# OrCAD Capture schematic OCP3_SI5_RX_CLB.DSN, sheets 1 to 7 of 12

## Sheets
1 PAGE01: title: OCP3 SI GEN 5 RX CLB; rev: X02; company: Dell, Inc.; note: C7D95; note: 200 Dell Way; note: Round Rock, TX 78682
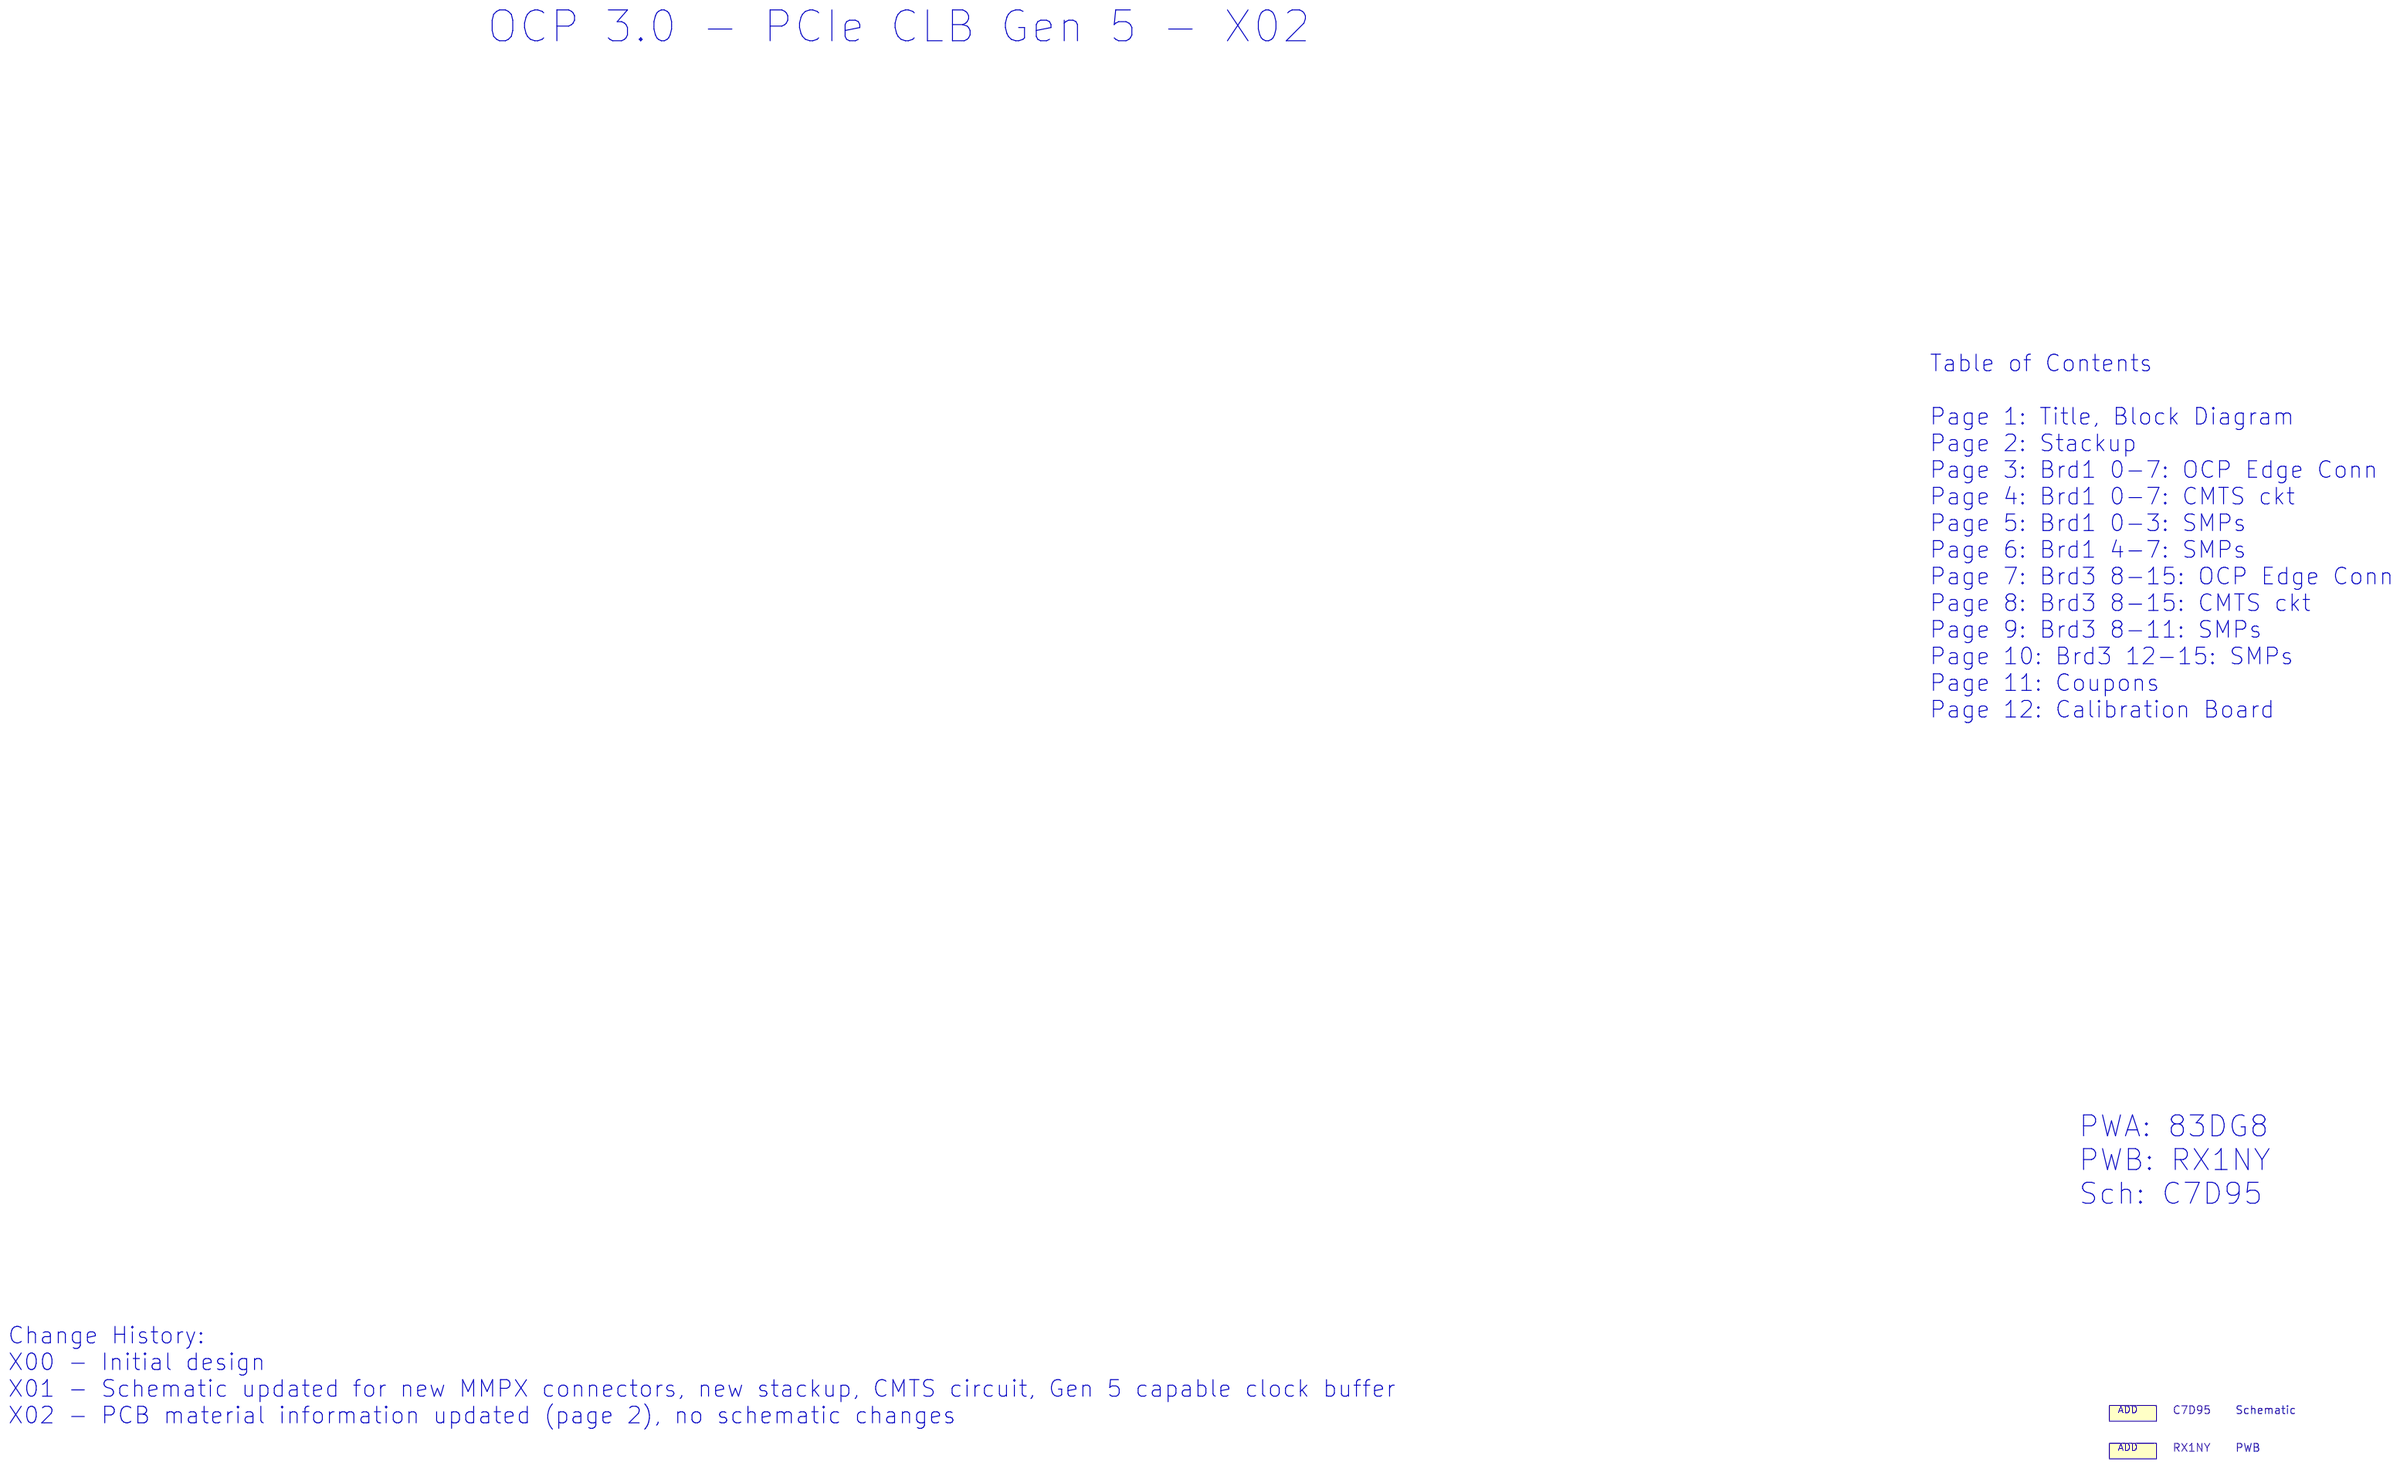
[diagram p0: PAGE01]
2 PAGE02
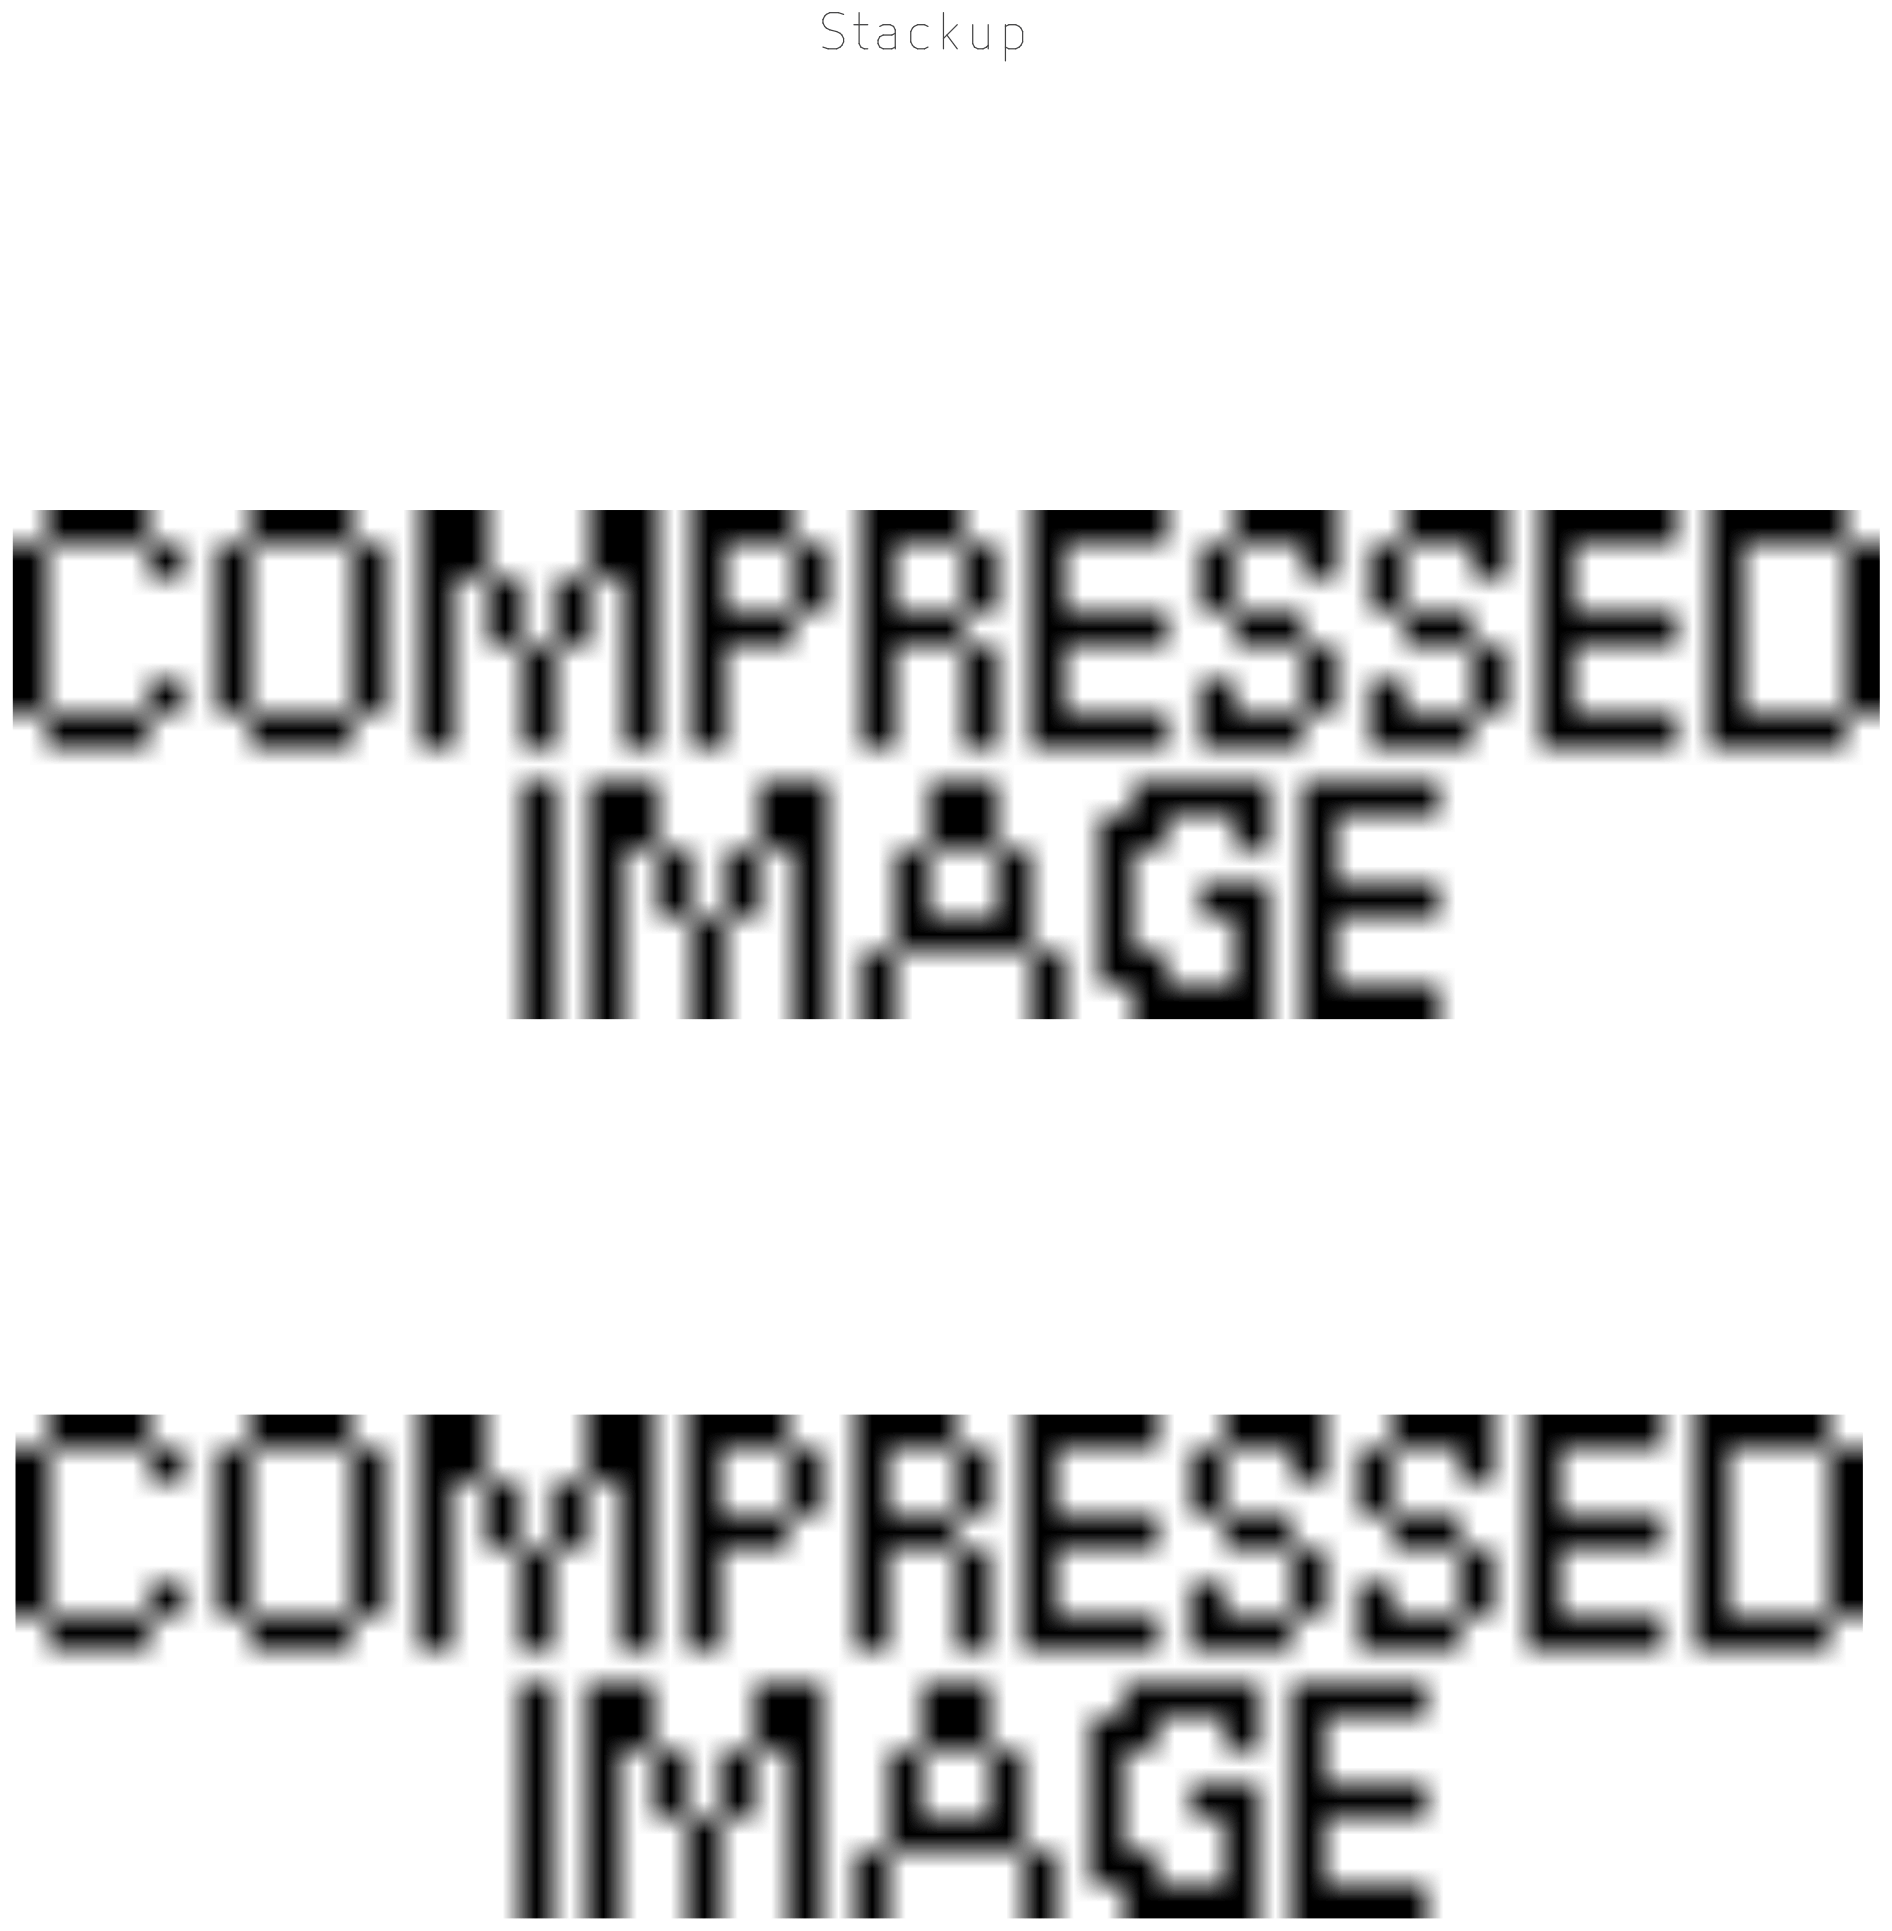
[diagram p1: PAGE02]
3 PAGE03: size Custom
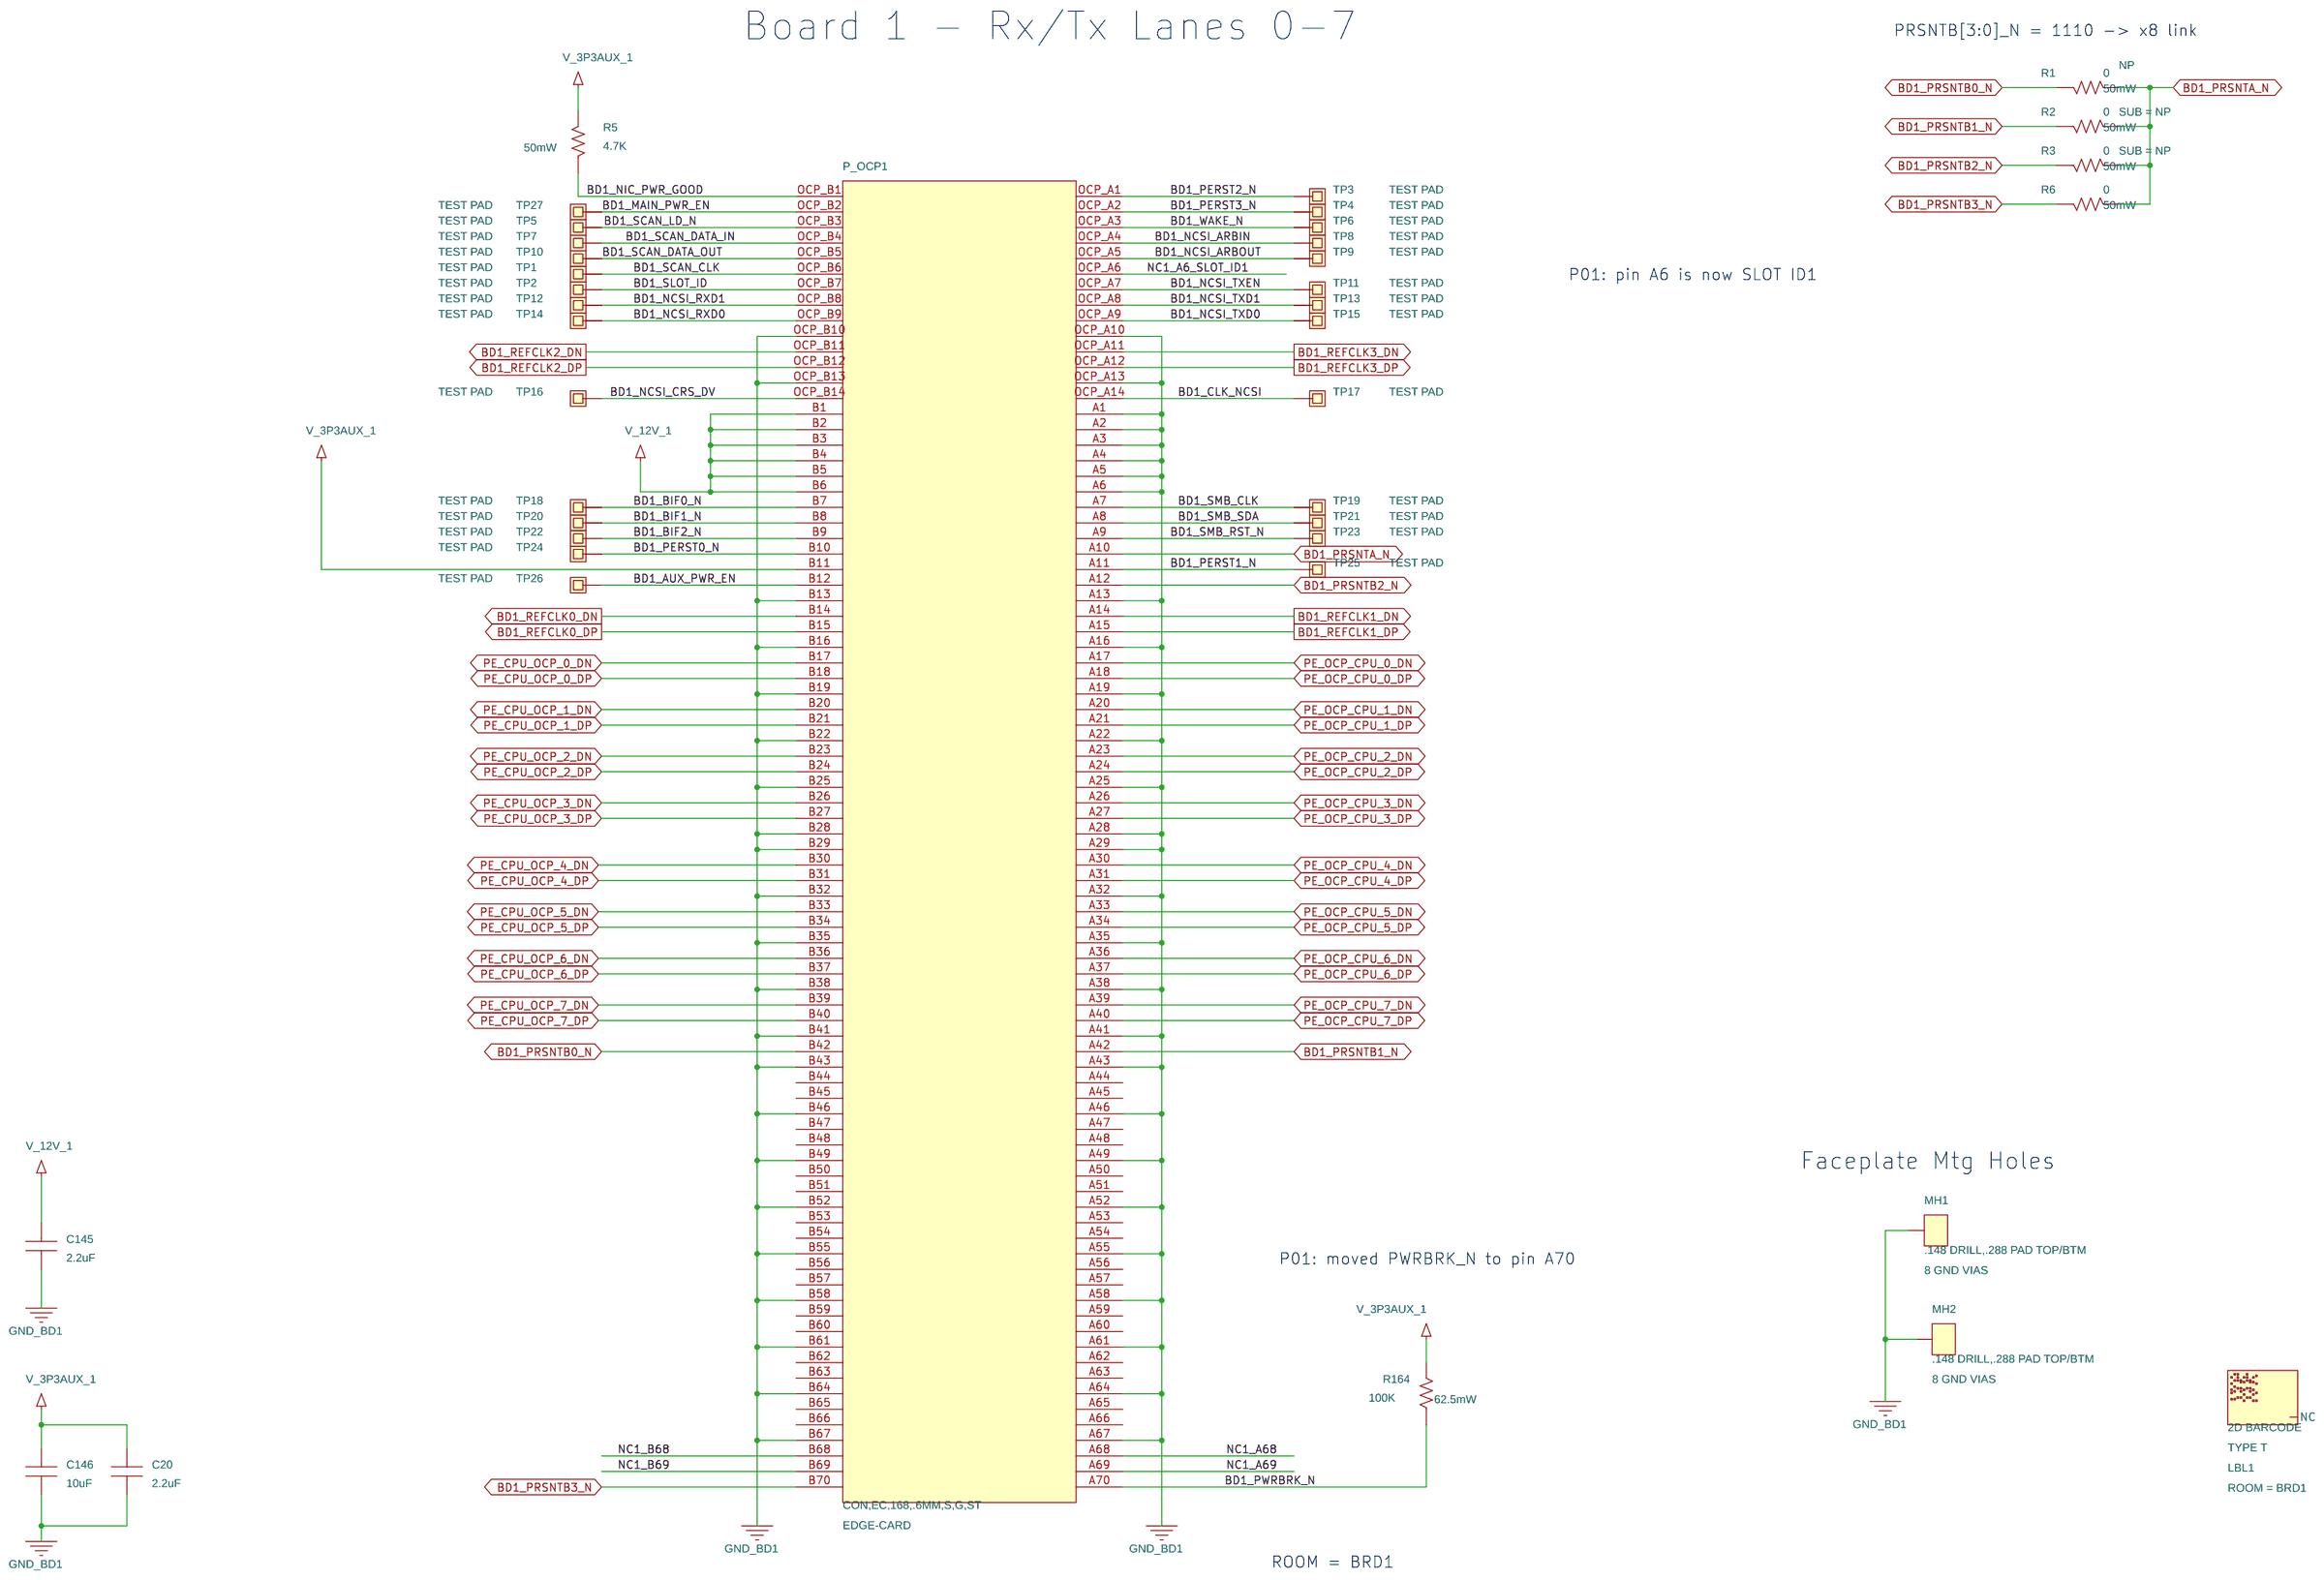
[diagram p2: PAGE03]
4 PAGE04: size Custom
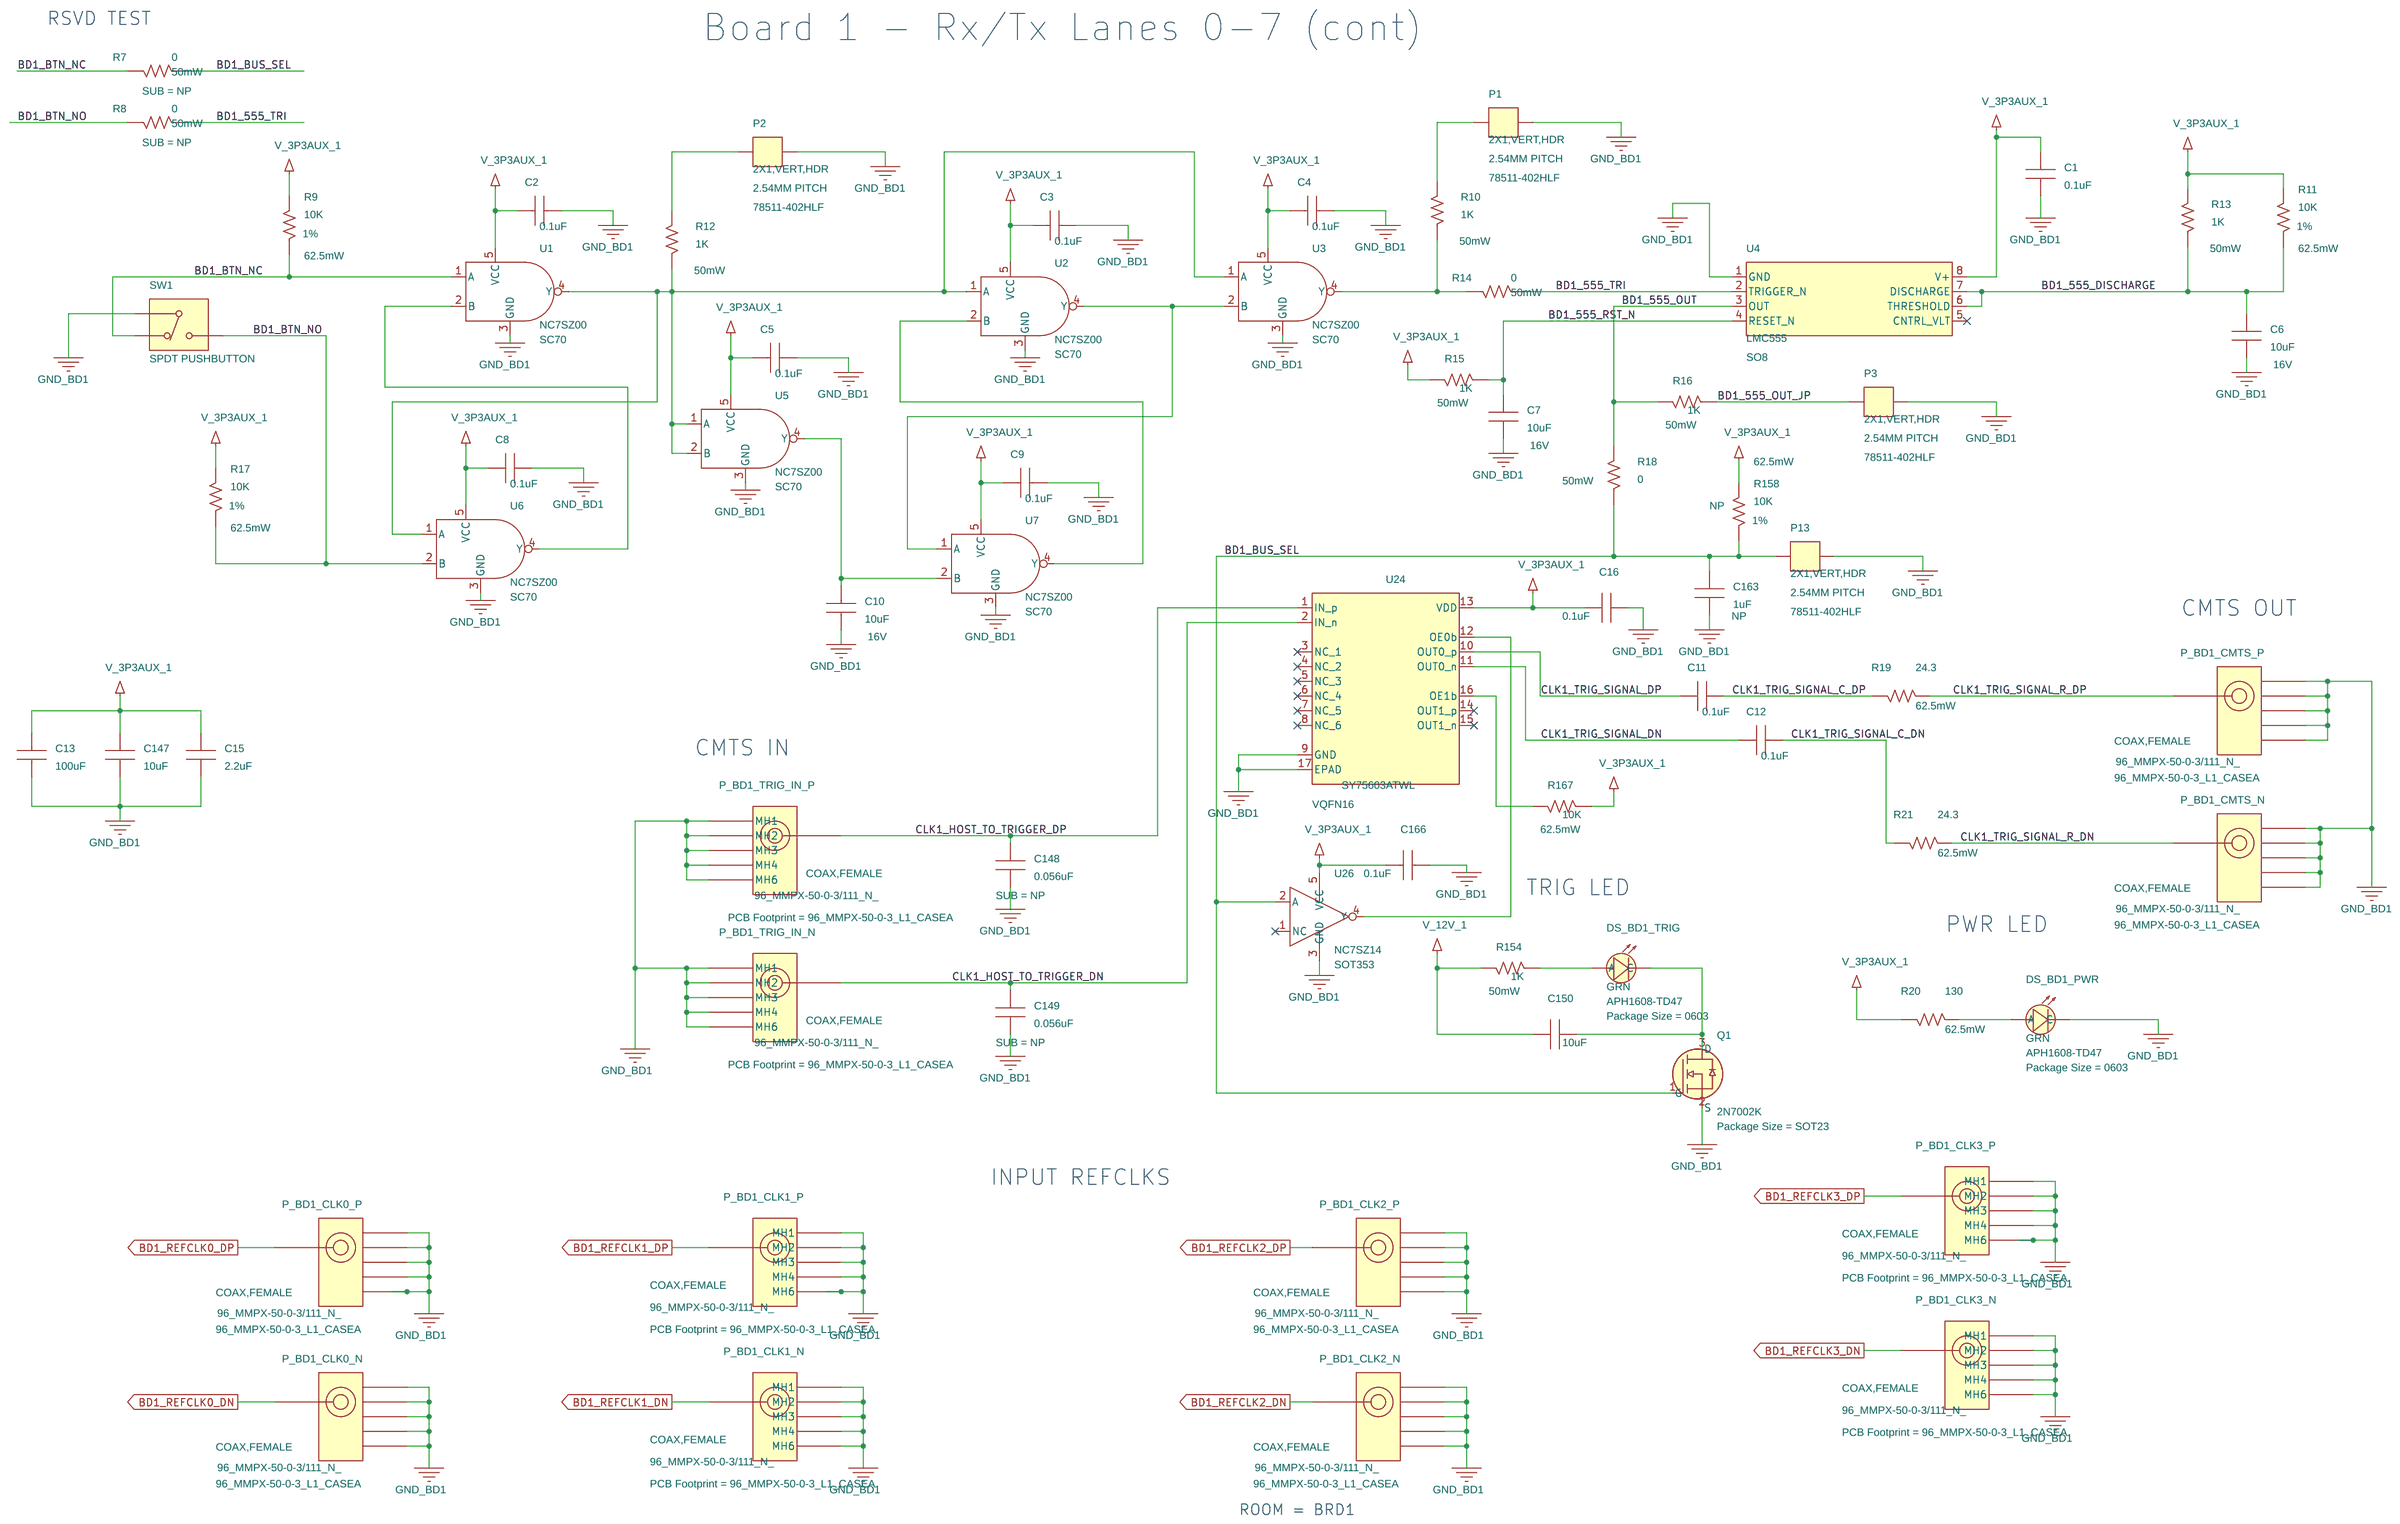
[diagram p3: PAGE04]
5 PAGE05: size Custom
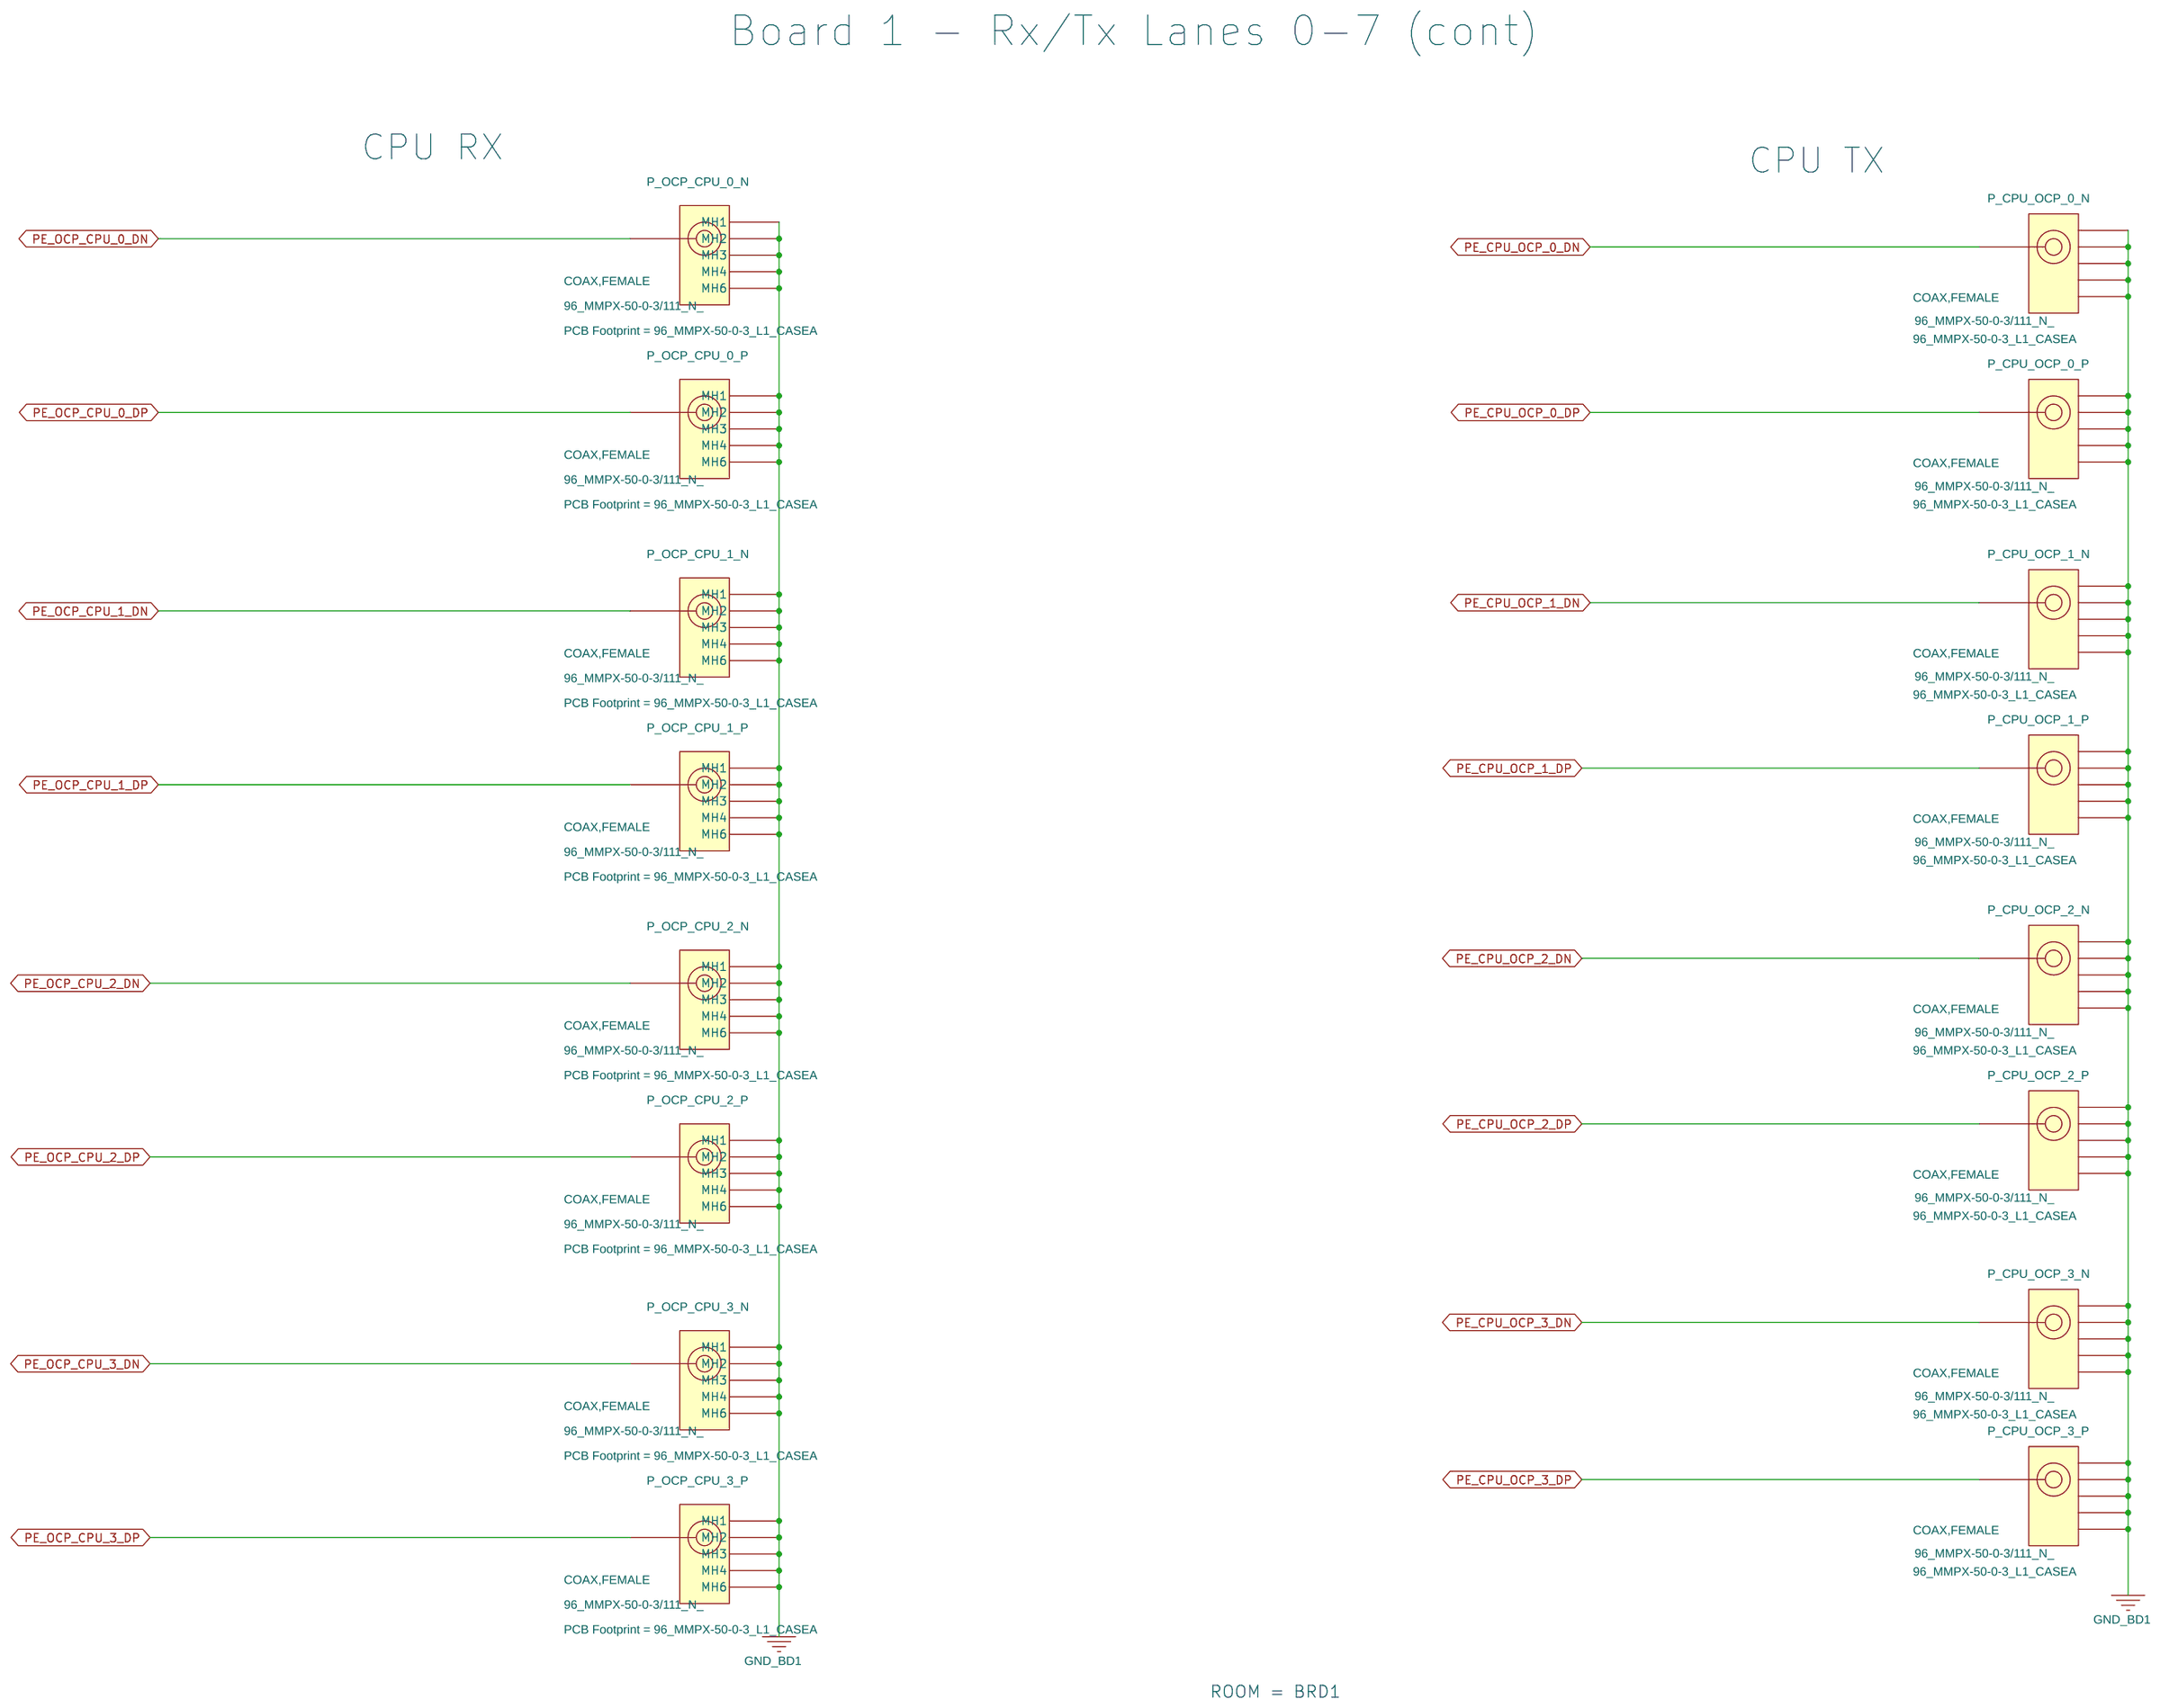
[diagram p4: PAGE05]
6 PAGE06: size Custom
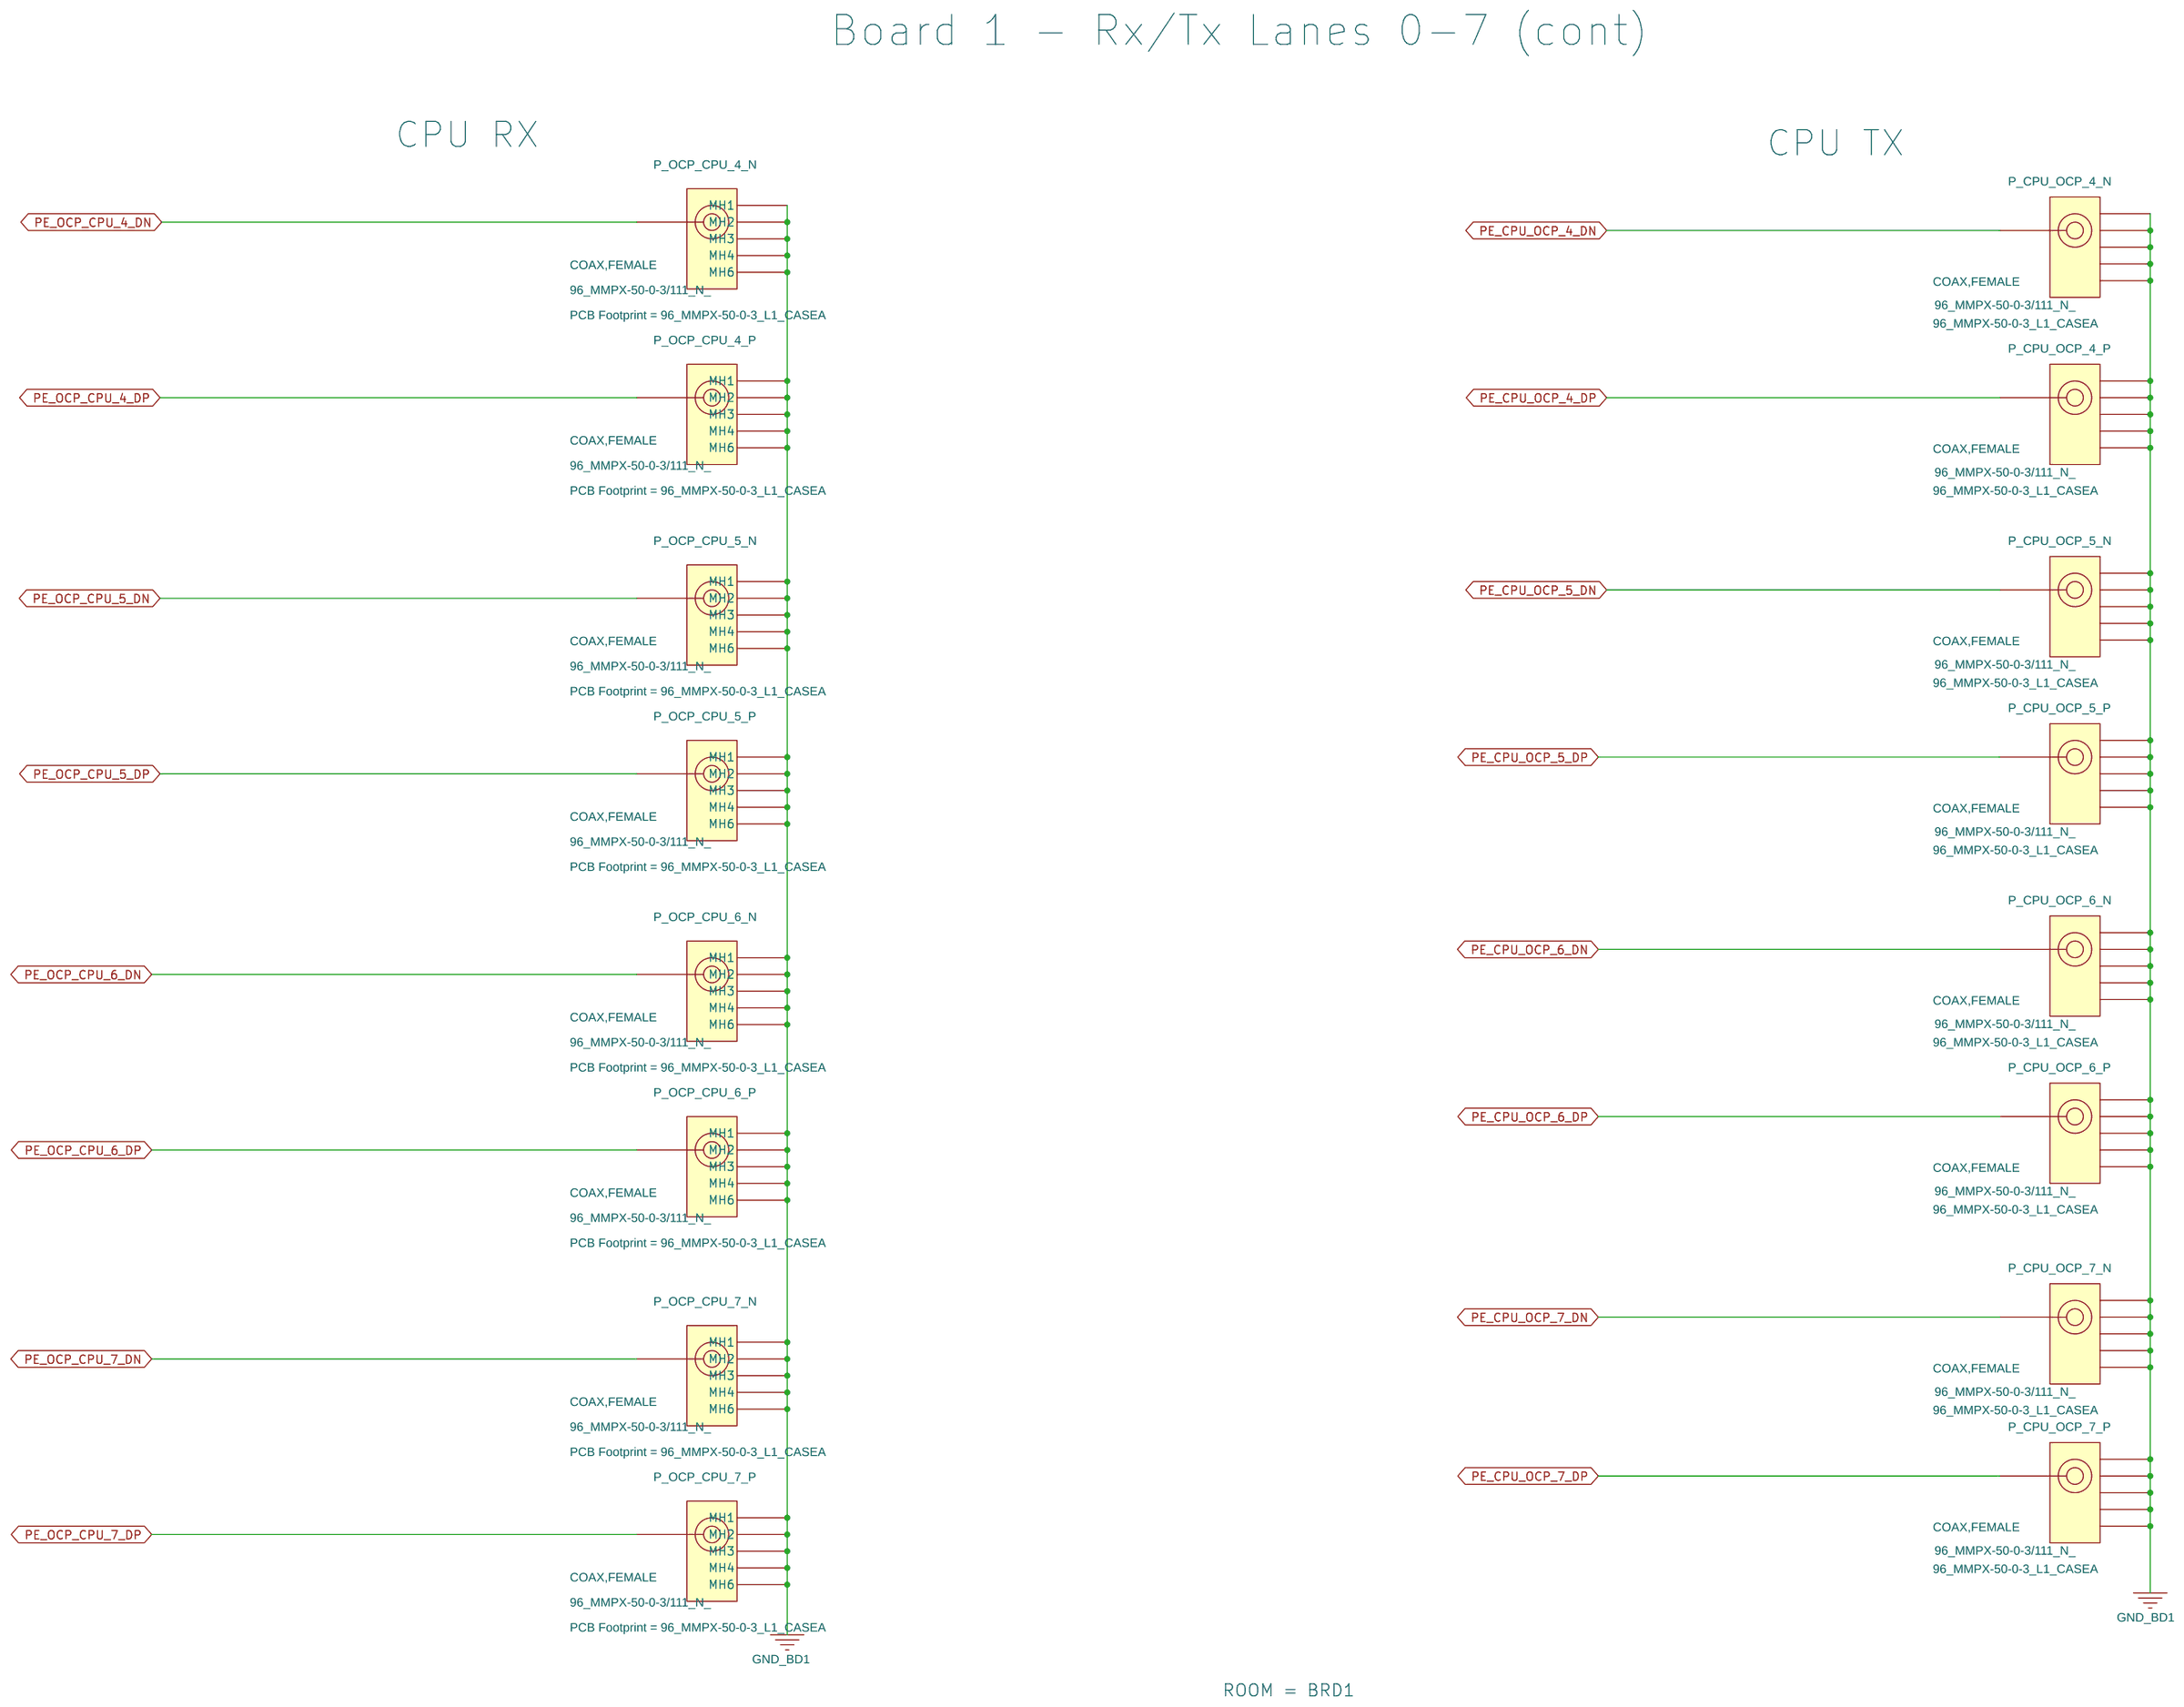
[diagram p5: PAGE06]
7 PAGE07: size Custom
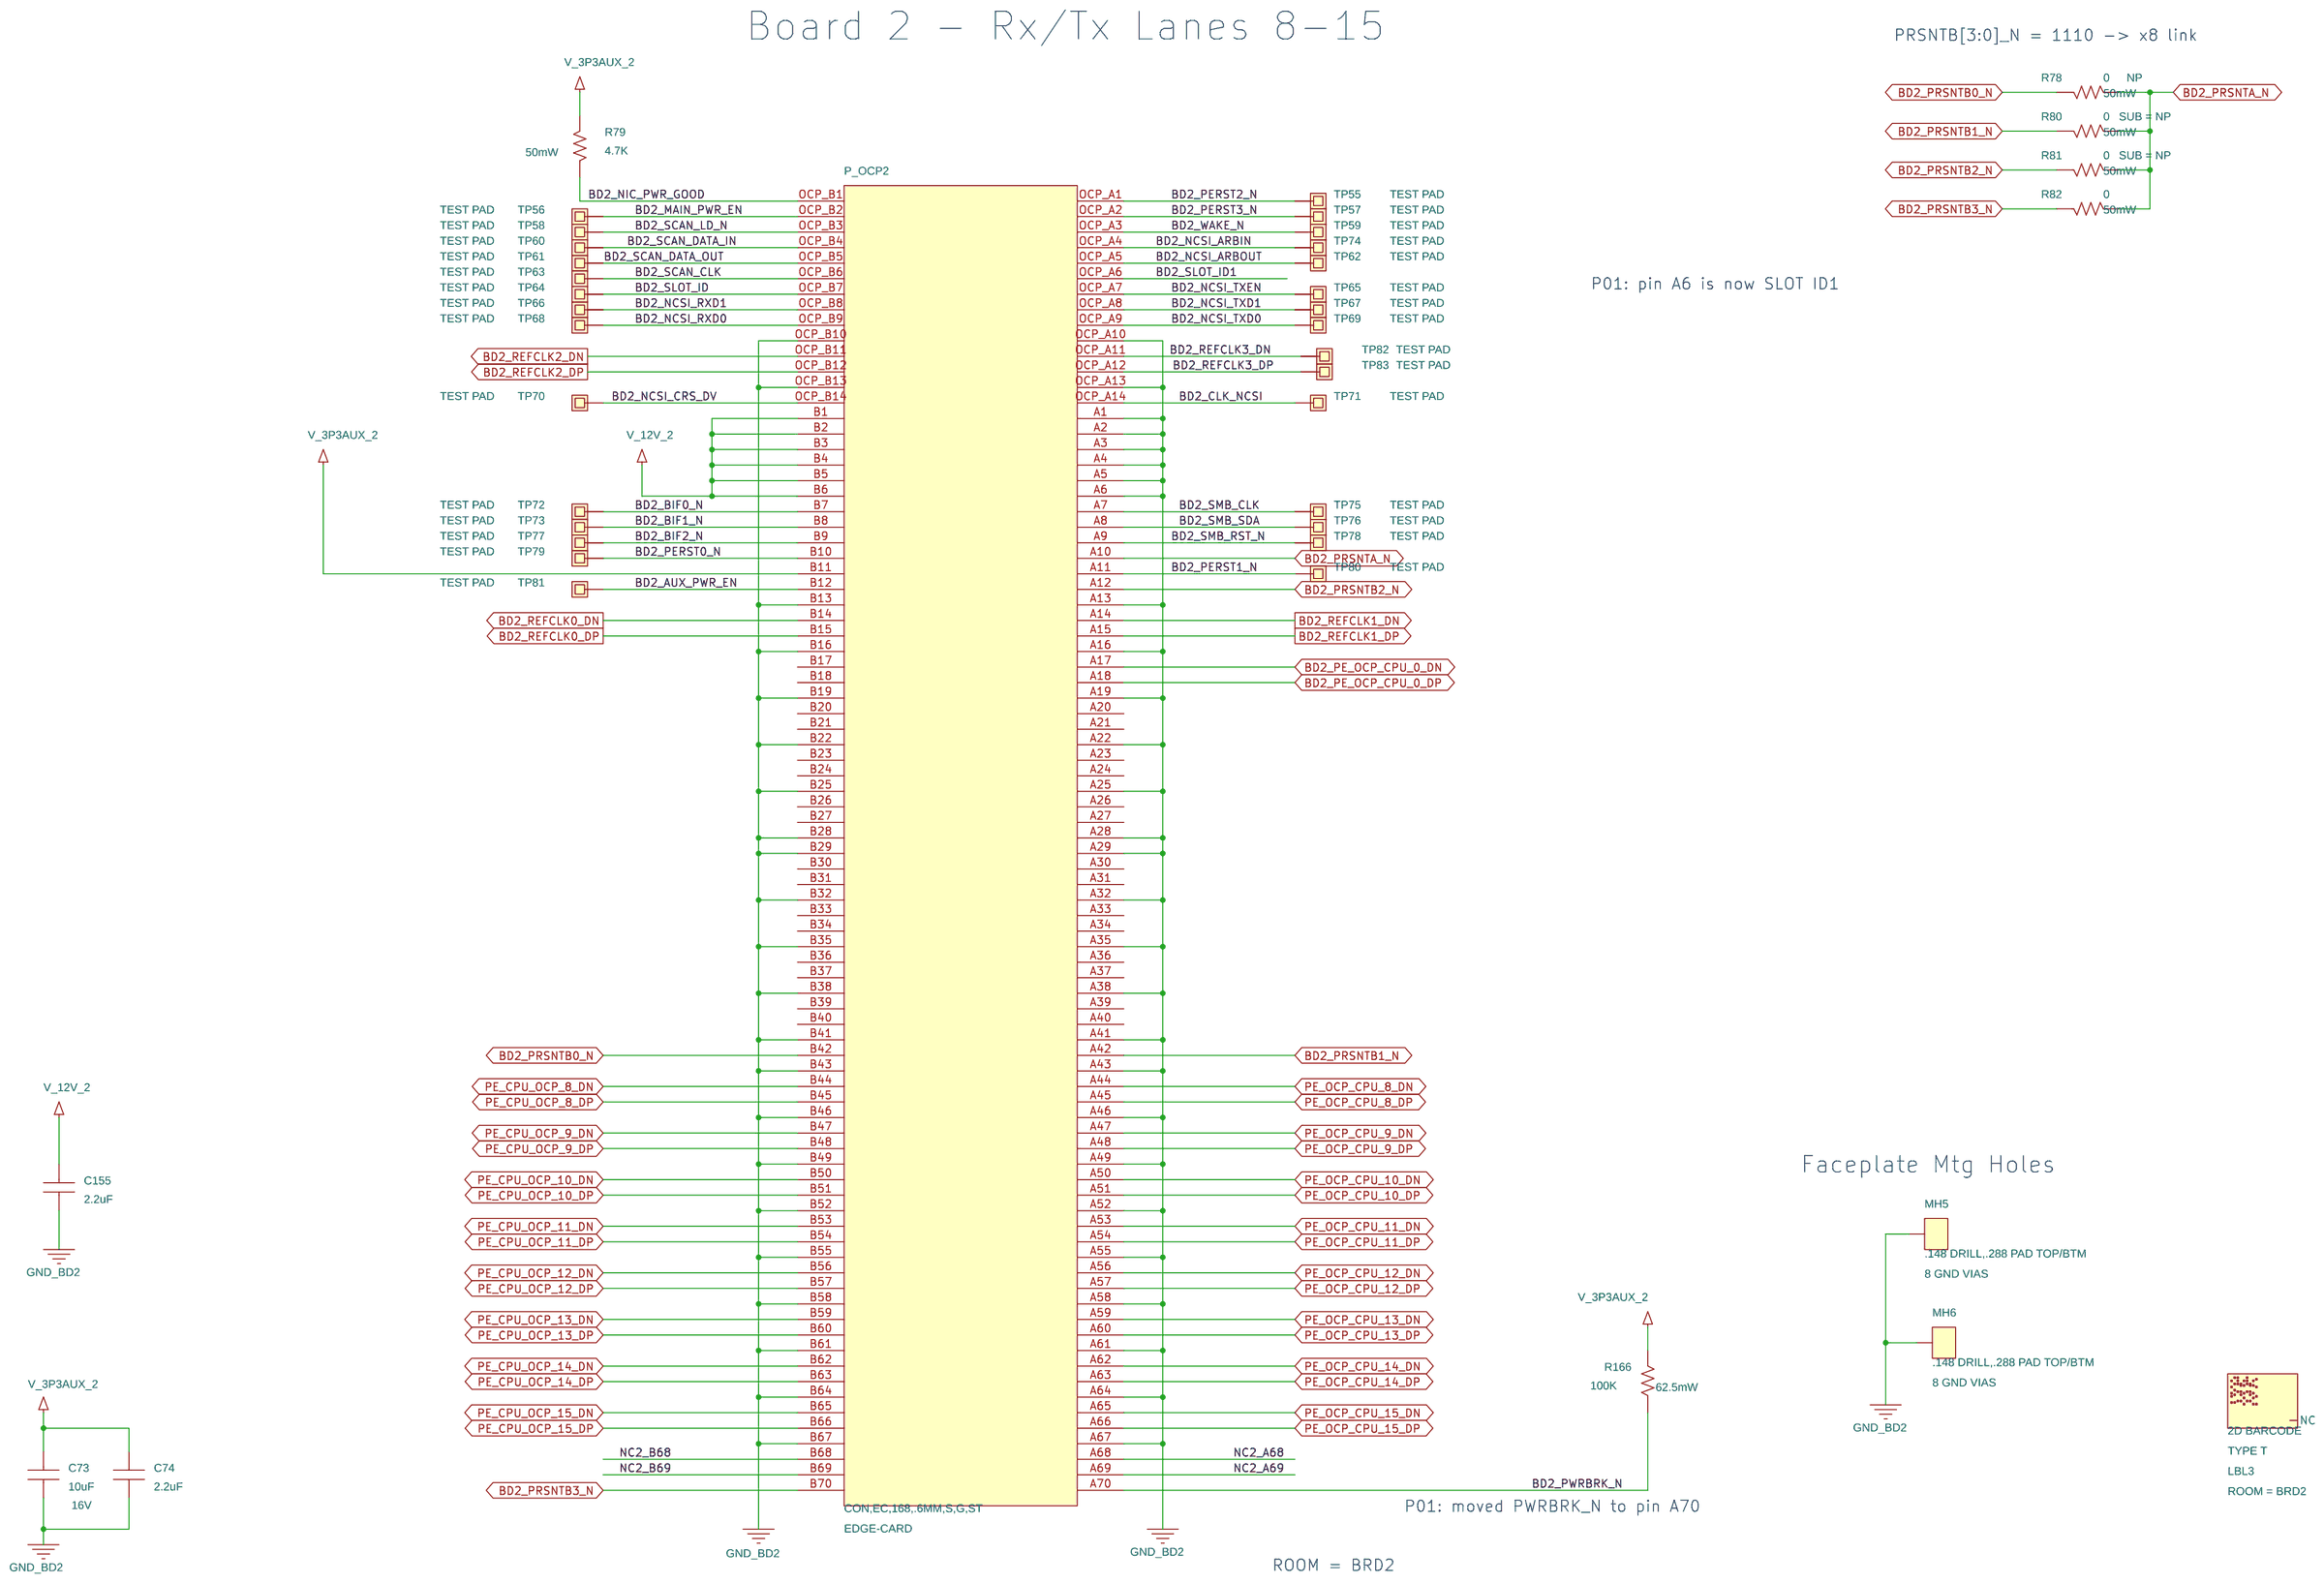
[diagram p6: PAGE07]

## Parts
sheet PAGE01
PWB  add_part
Schematic  add_part
sheet PAGE03
C20  2.2uF  [C0603]
C145  2.2uF  [C0603]
C146  10uF  [C0603]
LBL1  2d_label500x437  [2D_LABEL500X437]
MH1  .148 DRILL,.288 PAD TOP/BTM  [MH148_G8_288TB]
MH2  .148 DRILL,.288 PAD TOP/BTM  [MH148_G8_288TB]
P_OCP1  CON,EC,168,.6MM,S,G,ST  [CON_AMP_EDGE_ME101681340131X]
R1  0  [R0201]
R2  0  [R0201]
R3  0  [R0201]
R5  4.7K  [R0201]
R6  0  [R0201]
R164  100K  [R0402]
TP1  TEST PAD  [TP_REC1P00X1P50]
TP2  TEST PAD  [TP_REC1P00X1P50]
TP3  TEST PAD  [TP_REC1P00X1P50]
TP4  TEST PAD  [TP_REC1P00X1P50]
TP5  TEST PAD  [TP_REC1P00X1P50]
TP6  TEST PAD  [TP_REC1P00X1P50]
TP7  TEST PAD  [TP_REC1P00X1P50]
TP8  TEST PAD  [TP_REC1P00X1P50]
TP9  TEST PAD  [TP_REC1P00X1P50]
TP10  TEST PAD  [TP_REC1P00X1P50]
TP11  TEST PAD  [TP_REC1P00X1P50]
TP12  TEST PAD  [TP_REC1P00X1P50]
TP13  TEST PAD  [TP_REC1P00X1P50]
TP14  TEST PAD  [TP_REC1P00X1P50]
TP15  TEST PAD  [TP_REC1P00X1P50]
TP16  TEST PAD  [TP_REC1P00X1P50]
TP17  TEST PAD  [TP_REC1P00X1P50]
TP18  TEST PAD  [TP_REC1P00X1P50]
TP19  TEST PAD  [TP_REC1P00X1P50]
TP20  TEST PAD  [TP_REC1P00X1P50]
TP21  TEST PAD  [TP_REC1P00X1P50]
TP22  TEST PAD  [TP_REC1P00X1P50]
TP23  TEST PAD  [TP_REC1P00X1P50]
TP24  TEST PAD  [TP_REC1P00X1P50]
TP25  TEST PAD  [TP_REC1P00X1P50]
TP26  TEST PAD  [TP_REC1P00X1P50]
TP27  TEST PAD  [TP_REC1P00X1P50]
sheet PAGE04
C1  0.1uF  [C0201]
C2  0.1uF  [C0201]
C3  0.1uF  [C0201]
C4  0.1uF  [C0201]
C5  0.1uF  [C0201]
C6  10uF  [C0603]
C7  10uF  [C0603]
C8  0.1uF  [C0201]
C9  0.1uF  [C0201]
C10  10uF  [C0603]
C11  0.1uF  [C0201]
C12  0.1uF  [C0201]
C13  100uF  [C1210_107H]
C15  2.2uF  [C0603]
C16  0.1uF  [C0201]
C147  10uF  [C0603]
C148  0.056uF  [C0402]
C149  0.056uF  [C0402]
C150  10uF  [C0603]
C163  1uF  [C0603]
C166  0.1uF  [C0201]
DS_BD1_PWR  APH1608-TD47  [LEDC1608X65N]
DS_BD1_TRIG  APH1608-TD47  [LEDC1608X65N]
P1  2X1,VERT,HDR  [BERG1X2]
P2  2X1,VERT,HDR  [BERG1X2]
P3  2X1,VERT,HDR  [BERG1X2]
P13  2X1,VERT,HDR  [BERG1X2]
P_BD1_CLK0_N  COAX,FEMALE  [96_MMPX-50-0-3_L1_CASEA]
P_BD1_CLK0_P  COAX,FEMALE  [96_MMPX-50-0-3_L1_CASEA]
P_BD1_CLK1_N  COAX,FEMALE  [96_MMPX-50-0-3_L1_CASEA]
P_BD1_CLK1_P  COAX,FEMALE  [96_MMPX-50-0-3_L1_CASEA]
P_BD1_CLK2_N  COAX,FEMALE  [96_MMPX-50-0-3_L1_CASEA]
P_BD1_CLK2_P  COAX,FEMALE  [96_MMPX-50-0-3_L1_CASEA]
P_BD1_CLK3_N  COAX,FEMALE  [96_MMPX-50-0-3_L1_CASEA]
P_BD1_CLK3_P  COAX,FEMALE  [96_MMPX-50-0-3_L1_CASEA]
P_BD1_CMTS_N  COAX,FEMALE  [96_MMPX-50-0-3_L1_CASEA]
P_BD1_CMTS_P  COAX,FEMALE  [96_MMPX-50-0-3_L1_CASEA]
P_BD1_TRIG_IN_N  COAX,FEMALE  [96_MMPX-50-0-3_L1_CASEA]
P_BD1_TRIG_IN_P  COAX,FEMALE  [96_MMPX-50-0-3_L1_CASEA]
Q1  2N7002K  [SOT95P237X117_3N]
R7  0  [R0201]
R8  0  [R0201]
R9  10K  [R0402]
R10  1K  [R0201]
R11  10K  [R0402]
R12  1K  [R0201]
R13  1K  [R0201]
R14  0  [R0201]
R15  1K  [R0201]
R16  1K  [R0201]
R17  10K  [R0402]
R18  0  [R0201]
R19  24.3  [R0402]
R20  130  [R0402]
R21  24.3  [R0402]
R154  1K  [R0201]
R158  10K  [R0402]
R167  10K  [R0402]
SW1  SPDT PUSHBUTTON  [SW3PSMRA_2SH]
U1  NC7SZ00  [SOT65P210X110_5N]
U2  NC7SZ00  [SOT65P210X110_5N]
U3  NC7SZ00  [SOT65P210X110_5N]
U4  LMC555  [SOIC127P600X175_8N]
U5  NC7SZ00  [SOT65P210X110_5N]
U6  NC7SZ00  [SOT65P210X110_5N]
U7  NC7SZ00  [SOT65P210X110_5N]
U24  SY75603ATWL  [QFN50P300X300X90-17]
U26  NC7SZ14  [SOT65P210X110_5L]
sheet PAGE05
P_CPU_OCP_0_N  COAX,FEMALE  [96_MMPX-50-0-3_L1_CASEA]
P_CPU_OCP_0_P  COAX,FEMALE  [96_MMPX-50-0-3_L1_CASEA]
P_CPU_OCP_1_N  COAX,FEMALE  [96_MMPX-50-0-3_L1_CASEA]
P_CPU_OCP_1_P  COAX,FEMALE  [96_MMPX-50-0-3_L1_CASEA]
P_CPU_OCP_2_N  COAX,FEMALE  [96_MMPX-50-0-3_L1_CASEA]
P_CPU_OCP_2_P  COAX,FEMALE  [96_MMPX-50-0-3_L1_CASEA]
P_CPU_OCP_3_N  COAX,FEMALE  [96_MMPX-50-0-3_L1_CASEA]
P_CPU_OCP_3_P  COAX,FEMALE  [96_MMPX-50-0-3_L1_CASEA]
P_OCP_CPU_0_N  COAX,FEMALE  [96_MMPX-50-0-3_L1_CASEA]
P_OCP_CPU_0_P  COAX,FEMALE  [96_MMPX-50-0-3_L1_CASEA]
P_OCP_CPU_1_N  COAX,FEMALE  [96_MMPX-50-0-3_L1_CASEA]
P_OCP_CPU_1_P  COAX,FEMALE  [96_MMPX-50-0-3_L1_CASEA]
P_OCP_CPU_2_N  COAX,FEMALE  [96_MMPX-50-0-3_L1_CASEA]
P_OCP_CPU_2_P  COAX,FEMALE  [96_MMPX-50-0-3_L1_CASEA]
P_OCP_CPU_3_N  COAX,FEMALE  [96_MMPX-50-0-3_L1_CASEA]
P_OCP_CPU_3_P  COAX,FEMALE  [96_MMPX-50-0-3_L1_CASEA]
sheet PAGE06
P_CPU_OCP_4_N  COAX,FEMALE  [96_MMPX-50-0-3_L1_CASEA]
P_CPU_OCP_4_P  COAX,FEMALE  [96_MMPX-50-0-3_L1_CASEA]
P_CPU_OCP_5_N  COAX,FEMALE  [96_MMPX-50-0-3_L1_CASEA]
P_CPU_OCP_5_P  COAX,FEMALE  [96_MMPX-50-0-3_L1_CASEA]
P_CPU_OCP_6_N  COAX,FEMALE  [96_MMPX-50-0-3_L1_CASEA]
P_CPU_OCP_6_P  COAX,FEMALE  [96_MMPX-50-0-3_L1_CASEA]
P_CPU_OCP_7_N  COAX,FEMALE  [96_MMPX-50-0-3_L1_CASEA]
P_CPU_OCP_7_P  COAX,FEMALE  [96_MMPX-50-0-3_L1_CASEA]
P_OCP_CPU_4_N  COAX,FEMALE  [96_MMPX-50-0-3_L1_CASEA]
P_OCP_CPU_4_P  COAX,FEMALE  [96_MMPX-50-0-3_L1_CASEA]
P_OCP_CPU_5_N  COAX,FEMALE  [96_MMPX-50-0-3_L1_CASEA]
P_OCP_CPU_5_P  COAX,FEMALE  [96_MMPX-50-0-3_L1_CASEA]
P_OCP_CPU_6_N  COAX,FEMALE  [96_MMPX-50-0-3_L1_CASEA]
P_OCP_CPU_6_P  COAX,FEMALE  [96_MMPX-50-0-3_L1_CASEA]
P_OCP_CPU_7_N  COAX,FEMALE  [96_MMPX-50-0-3_L1_CASEA]
P_OCP_CPU_7_P  COAX,FEMALE  [96_MMPX-50-0-3_L1_CASEA]
sheet PAGE07
C73  10uF  [C0603]
C74  2.2uF  [C0603]
C155  2.2uF  [C0603]
LBL3  2d_label500x437  [2D_LABEL500X437]
MH5  .148 DRILL,.288 PAD TOP/BTM  [MH148_G8_288TB]
MH6  .148 DRILL,.288 PAD TOP/BTM  [MH148_G8_288TB]
P_OCP2  CON,EC,168,.6MM,S,G,ST  [CON_AMP_EDGE_ME101681340131X]
R78  0  [R0201]
R79  4.7K  [R0201]
R80  0  [R0201]
R81  0  [R0201]
R82  0  [R0201]
R166  100K  [R0402]
TP55  TEST PAD  [TP_REC1P00X1P50]
TP56  TEST PAD  [TP_REC1P00X1P50]
TP57  TEST PAD  [TP_REC1P00X1P50]
TP58  TEST PAD  [TP_REC1P00X1P50]
TP59  TEST PAD  [TP_REC1P00X1P50]
TP60  TEST PAD  [TP_REC1P00X1P50]
TP61  TEST PAD  [TP_REC1P00X1P50]
TP62  TEST PAD  [TP_REC1P00X1P50]
TP63  TEST PAD  [TP_REC1P00X1P50]
TP64  TEST PAD  [TP_REC1P00X1P50]
TP65  TEST PAD  [TP_REC1P00X1P50]
TP66  TEST PAD  [TP_REC1P00X1P50]
TP67  TEST PAD  [TP_REC1P00X1P50]
TP68  TEST PAD  [TP_REC1P00X1P50]
TP69  TEST PAD  [TP_REC1P00X1P50]
TP70  TEST PAD  [TP_REC1P00X1P50]
TP71  TEST PAD  [TP_REC1P00X1P50]
TP72  TEST PAD  [TP_REC1P00X1P50]
TP73  TEST PAD  [TP_REC1P00X1P50]
TP74  TEST PAD  [TP_REC1P00X1P50]
TP75  TEST PAD  [TP_REC1P00X1P50]
TP76  TEST PAD  [TP_REC1P00X1P50]
TP77  TEST PAD  [TP_REC1P00X1P50]
TP78  TEST PAD  [TP_REC1P00X1P50]
TP79  TEST PAD  [TP_REC1P00X1P50]
TP80  TEST PAD  [TP_REC1P00X1P50]
TP81  TEST PAD  [TP_REC1P00X1P50]
TP82  TEST PAD  [TP_REC1P00X1P50]
TP83  TEST PAD  [TP_REC1P00X1P50]

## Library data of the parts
PWB = add_part: Part Number: RX1NY
Schematic = add_part: Part Number: C7D95
C15 C20 C145 = cap: CAP,2.2UF,10%,16V,X5R,0603; CLASS: DISCRETE; DPN: J6201; Dielectric Type: X5R; Lead Free: Yes; Lifecycle Phase: A Revision; Manufacturer: MURATA ERIE; Manufacturer PN: GRM188R61C225KE15D; Package Height: 40 MIL; Package Size: 0603; Package Type: SMD; Part Number: J6201; ROOM: BRD1; Rev: A00-00; Tolerance: 10%; Voltage: 16V
C146 C147 C150 = cap: CAP,10UF,20%,16V,X6S,0603; CLASS: DISCRETE; DPN: 3MRV8; Dielectric Type: X6S; Lead Free: Yes; Lifecycle Phase: A Revision; Manufacturer: MURATA ERIE; Manufacturer PN: GRM188C81C106MA73D; Package Height: 40 MIL; Package Size: 0603; Package Type: SMD; Part Number: 3MRV8; ROOM: BRD1; Rev: A00-00; Tolerance: 20%; Voltage: 16V
LBL1 = 2d_label500x437: LABEL,2D BARCODE,.500X.437,TYPE T; DEVICE: 090730100102; Part Number: HP126; ROOM: BRD1; TAG1: 2D BARCODE; TAG2: TYPE T
MH1 MH2 = g_1x1_mh: MT_HOLE_UNPLATED148_288PADS TOP AND BOTTOM_8GND VIAS; BOM_IGNORE: TRUE; CLASS: DISCRETE; DPN: 00000; GND Vias: 8 GND VIAS; Lead Free: N/A; Lifecycle Phase: N/A; Package Height: 1 MIL; Part Number: 090730100124; ROOM: BRD1; Rev: N/A
P_OCP1 = c84edg_amp: [EDGE CARD]CON,EC,168,.6MM,S,G,ST; ALT_SYMBOLS: (CON_AMP_EDGE_ME101681340131X_alt); BOM_IGNORE: TRUE; CLASS: IO; Connector Type: EDGE-CARD; DPN: 00000_7HYMF; Lead Free: N/A; Lifecycle Phase: N/A; Package Height: 0.98 MM; Package Type: EDGE-CARD; Part Number: 7HYMF|EDG; ROOM: BRD1; Rev: N/A
R1-R3 R7 R8 = res: RES,0,1/20W,5%,THKFLM,0201; ALT_SYMBOLS: (R0201_R4,R0201M_FOX); CLASS: DISCRETE; DPN: YY941; Lead Free: Yes; Lifecycle Phase: A Revision; Manufacturer: KOA; Manufacturer PN: RK73Z1HTQTC; Material: Thick Film; Package Height: 0.33 MM; Package Size: 0201; Package Type: SMD; Part Number: YY941; ROOM: BRD1; Rated Power: 50mW; Rev: A00-00; SUB: NP; Tolerance: 5%
R5 = res: RES,4.7K,1/20W,1%,THKFLM,0201; ALT_SYMBOLS: (R0201_R4,R0201M_FOX); CLASS: DISCRETE; DPN: X44H2; Lead Free: Yes; Lifecycle Phase: A Revision; Manufacturer: KOA; Manufacturer PN: RK73H1HTTC4701F; Material: Thick Film; Package Height: 0.33 MM; Package Size: 0201; Package Type: SMD; Part Number: X44H2; ROOM: BRD1; Rated Power: 50mW; Rev: A00-00; Tolerance: 1%
R6 R14 R18 = res: RES,0,1/20W,5%,THKFLM,0201; ALT_SYMBOLS: (R0201_R4,R0201M_FOX); CLASS: DISCRETE; DPN: YY941; Lead Free: Yes; Lifecycle Phase: A Revision; Manufacturer: KOA; Manufacturer PN: RK73Z1HTQTC; Material: Thick Film; Package Height: 0.33 MM; Package Size: 0201; Package Type: SMD; Part Number: YY941; ROOM: BRD1; Rated Power: 50mW; Rev: A00-00; Tolerance: 5%
R164 = res: RES,100K,1/16W,5%,THKFLM,0402; CLASS: DISCRETE; DPN: 92259; Lead Free: Yes; Lifecycle Phase: A Revision; Manufacturer: KOA; Manufacturer PN: RK73B1ETTP104J; Material: Thick Film; Package Height: 16 MIL; Package Size: 0402; Package Type: SMD; Part Number: 92259; ROOM: BRD1; Rated Power: 62.5mW; Rev: A00-00; Tolerance: 5%
TP1-TP27 = g_tp: TEST POINT 1.00X1.50; BOM_IGNORE: TRUE; CLASS: DISCRETE; DPN: 00000; Lead Free: N/A; Lifecycle Phase: N/A; Package Type: SMD; Part Number: 140114160012; ROOM: BRD1; Rev: N/A
C1-C5 C8 C9 C11 C12 C16 = cap: CAP,0.1UF,10%,10V,X5R,0201; ALT_SYMBOLS: (CAPC0603X33N,C0201M_FOX,C0201_R4); CLASS: DISCRETE; DPN: MNN3J; Dielectric Type: X5R; Lead Free: Yes; Lifecycle Phase: A Revision; Manufacturer: DARFON ELECTRONICS CORP; Manufacturer PN: C0603X5R104KDT; Package Height: 0.33 MM; Package Size: 0201; Package Type: SMD; Part Number: MNN3J; ROOM: BRD1; Rev: A00-00; Tolerance: 10%; Voltage: 10V
C6 C7 C10 = cap: CAP,10UF,20%,16V,X6S,0603; CLASS: DISCRETE; DEVICE: 090729120217; DPN: 3MRV8; Dielectric Type: X6S; Lead Free: Yes; Lifecycle Phase: A Revision; Manufacturer: MURATA ERIE; Manufacturer PN: GRM188C81C106MA73D; Package Height: 40 MIL; Package Size: 0603; Package Type: SMD; Part Number: 3MRV8; ROOM: BRD1; Rev: A00-00; TOLERANCE: 20%; VOLTAGE: 16V
C13 = cap: CAP,100UF,20%,6.3V,X5R,1210; CLASS: DISCRETE; DPN: DN761; Dielectric Type: X5R; Lead Free: Yes; Lifecycle Phase: A Revision; Manufacturer: MURATA ERIE; Manufacturer PN: GRM32ER60J107ME20L; Package Height: 107 MIL; Package Size: 1210; Package Type: SMD; Part Number: DN761; ROOM: BRD1; Rev: A00-00; Tolerance: 20%; Voltage: 6.3V
C148 C149 = cap: CAP,0.056UF,10%,10V,X7R,0402; CLASS: DISCRETE; DPN: KN9YT; Dielectric Type: X7R; Lead Free: Yes; Lifecycle Phase: Preliminary; Manufacturer: SAMSUNG; Manufacturer PN: CL05B563KP5NNNC; Package Height: 24 MIL; Package Size: 0402; Package Type: SMD; Part Number: KN9YT; ROOM: BRD1; Rev: Introductory; SUB: NP; Tolerance: 10%; Voltage: 10V
C163 = cap: CAP,1UF,10%,16V,X7R,0603; CLASS: DISCRETE; DPN: RY497; Dielectric Type: X7R; Lead Free: Yes; Lifecycle Phase: A Revision; Manufacturer: KEMET ELECTRONICS; Manufacturer PN: C0603C105K4RAC; Package Height: 40 MIL; Package Size: 0603; Package Type: SMD; Part Number: RY497; ROOM: BRD1; Rev: A00-00; SUB: NP; Tolerance: 10%; Voltage: 16V
C166 = cap: CAP,0.1UF,10%,10V,X5R,0201; ALT_SYMBOLS: (CAPC0603X33N,C0201M_FOX,C0201_R4); CLASS: DISCRETE; DPN: MNN3J; Dielectric Type: X5R; Lead Free: Yes; Lifecycle Phase: A Revision; Manufacturer: DARFON ELECTRONICS CORP; Manufacturer PN: C0603X5R104KDT; Package Height: 0.33 MM; Package Size: 0201; Package Type: SMD; Part Number: MNN3J; ROOM: BRD2; Rev: A00-00; Tolerance: 10%; Voltage: 10V
DS_BD1_PWR DS_BD1_TRIG = g_led_a1_c2: LED,0603,CLR,GRN,2V,20MA,35MCD; CLASS: DISCRETE; DPN: UJ387; LED Color: GRN; Lead Free: Yes; Lifecycle Phase: A Revision; Manufacturer: KINGBRIGHT CORPORATION; Package Height: 0.65 MM; Package Size: 0603; Package Type: SMD; Part Number: UJ387; ROOM: BRD1; Rev: A01-00; Voltage: 2V
P1-P3 P13 = g_2x1: CON,HDR,1X2,M,.1X.32,S,T,U,TH; CLASS: IO; DPN: RD013; Lead Free: Yes; Lifecycle Phase: A Revision; Manufacturer: FCI; Manufacturer PN: 78511-402HLF; Package Height: 426 MIL; Package Size: HDR1X2; Package Type: TH; Part Number: RD013; Pin Info: 2.54MM PITCH; ROOM: BRD1; Rev: A00-00
P_BD1_CLK0_N P_BD1_CLK0_P P_BD1_CLK2_N P_BD1_CLK2_P P_BD1_CMTS_N P_BD1_CMTS_P P_CPU_OCP_0_N P_CPU_OCP_0_P P_CPU_OCP_1_N P_CPU_OCP_1_P P_CPU_OCP_2_N P_CPU_OCP_2_P P_CPU_OCP_3_N P_CPU_OCP_3_P P_CPU_OCP_4_N P_CPU_OCP_4_P P_CPU_OCP_5_N P_CPU_OCP_5_P P_CPU_OCP_6_N P_CPU_OCP_6_P P_CPU_OCP_7_N P_CPU_OCP_7_P = g_jack_0: CON,HDR,COAXIAL,F,G,SMT; ALT_SYMBOLS: (96_mmpx-50-0-3_l6_casea); Manufacturer: HUBBLE INC; Manufacturer PN: 96_MMPX-50-0-3/111_N_; Package Height: 247 MIL; Package Type: SMD/TH; Part Number: 50Y9H
P_BD1_CLK1_N P_BD1_CLK1_P P_BD1_CLK3_N P_BD1_CLK3_P P_BD1_TRIG_IN_N P_BD1_TRIG_IN_P P_OCP_CPU_0_N P_OCP_CPU_0_P P_OCP_CPU_1_N P_OCP_CPU_1_P P_OCP_CPU_2_N P_OCP_CPU_2_P P_OCP_CPU_3_N P_OCP_CPU_3_P P_OCP_CPU_4_N P_OCP_CPU_4_P P_OCP_CPU_5_N P_OCP_CPU_5_P P_OCP_CPU_6_N P_OCP_CPU_6_P P_OCP_CPU_7_N P_OCP_CPU_7_P = g_jack_1: CON,HDR,COAXIAL,F,G,SMT; ALT_SYMBOLS: (96_mmpx-50-0-3_l6_casea); DPN: WD7FW; Lead Free: Yes; Lifecycle Phase: Preliminary; Manufacturer: HUBBLE INC; Manufacturer PN: 96_MMPX-50-0-3/111_N_; Package Height: 247 MIL; Package Type: SMD/TH; Part Number: 50Y9H; ROOM: BRD1; Rev: Introductory
Q1 = ft2n7002k_sot23: TRANS,FET,NCHN,60V,SOT23,ESD1K; CLASS: DISCRETE; DPN: FR033; Lead Free: Yes; Lifecycle Phase: A Revision; Manufacturer: NXP SEMICONDUCTOR; Package Height: 1.17 MM; Package Size: SOT23; Package Type: SMD; Part Number: FR033; Polarity: N-Channel; ROOM: BRD1; Rated Voltage: 60V; Rev: A00-00
R9 R11 R17 = res: RES,10K,1/16W,1%,THKFLM,0402; DEVICE: 090729121122; Part Number: N1256; ROOM: BRD1; Rated Power: 62.5mW; TOLERANCE: 1%
R10 R12 R13 R15 R16 R154 = res: RES,1K,1/20W,1%,THKFLM,0201; ALT_SYMBOLS: (R0201_R4,R0201M_FOX); CLASS: DISCRETE; DPN: 3WWMJ; Lead Free: Yes; Lifecycle Phase: A Revision; Manufacturer: KOA; Manufacturer PN: RK73H1HTQTC1001F; Material: Thick Film; Package Height: 0.33 MM; Package Size: 0201; Package Type: SMD; Part Number: 3WWMJ; ROOM: BRD1; Rated Power: 50mW; Rev: A00-00; Tolerance: 1%
R19 R21 = res: RES,24.3,1/16W,1%,THKFLM,0402; CLASS: DISCRETE; DPN: H8992; Lead Free: Yes; Lifecycle Phase: A Revision; Manufacturer: KOA; Manufacturer PN: RK73H1ET-24R3F; Material: Thick Film; Package Height: 16 MIL; Package Size: 0402; Package Type: SMD; Part Number: H8992; ROOM: BRD1; Rated Power: 62.5mW; Rev: A00-00; Tolerance: 1%
R20 = res: RES,130,1/16W,1%,THKFLM,0402; CLASS: DISCRETE; DPN: J8387; Lead Free: Yes; Lifecycle Phase: A Revision; Manufacturer: KOA; Manufacturer PN: RK73H1ETTP1300F; Material: Thick Film; Package Height: 16 MIL; Package Size: 0402; Package Type: SMD; Part Number: J8387; ROOM: BRD1; Rated Power: 62.5mW; Rev: A00-00; Tolerance: 1%
R158 = res: RES,10K,1/16W,1%,THKFLM,0402; DEVICE: 090729121122; Part Number: N1256; ROOM: BRD1; Rated Power: 62.5mW; SUB: NP; TOLERANCE: 1%
R167 = res: RES,10K,1/16W,1%,THKFLM,0402; CLASS: DISCRETE; DPN: 3WWMJ; Lead Free: Yes; Lifecycle Phase: A Revision; Manufacturer: KOA; Manufacturer PN: RK73H1ETTP1002F; Material: Thick Film; Package Height: 16 MIL; Package Size: 0402; Package Type: SMD; Part Number: N1256; ROOM: BRD1; Rated Power: 62.5mW; Rev: A00-00; Tolerance: 1%
SW1 = sw3psmra_spdt: SWT,PB,SPDT,ON-MOM,SMT; CLASS: DISCRETE; DPN: GC8VG; Lead Free: Yes; Lifecycle Phase: X Revision; Manufacturer: C&K; Manufacturer PN: EP12SD1SAPE; Package Height: 5.08 MM; Package Type: SMD; Part Number: GC8VG; ROOM: BRD1; Rev: X00-00; Switch Configuration: SPDT; Switch Type: PUSHBUTTON
U1-U3 U5-U7 = g_nand_1slot_a1_b2: IC,NC7SZ00,SC70,2-INPUT-NAND; CLASS: IC; DPN: RPWR7; Lead Free: Yes; Lifecycle Phase: A Revision; Manufacturer: FAIRCHILD; Manufacturer PN: NC7SZ00P5X; Package Height: 1.1 MM; Package Size: SC70; Package Type: SMD; Part Number: RPWR7; ROOM: BRD1; Rev: A00-00
U4 = lmc555: IC,C555,SO8,CMOS TIMER; CLASS: IC; DPN: 83011; Lead Free: No; Lifecycle Phase: A Revision; Manufacturer: NATIONAL SEMICONDUCTOR; Manufacturer PN: LMC555CM; Package Height: 1.75 MM; Package Size: SO8; Package Type: SMD; Part Number: 83011; ROOM: BRD1; Rev: A00-00
U24 = SY75603ATWL: IC,PCEI CLKBUFF,2OUTPUT,VQFN16; Manufacturer: MICROCHIP TECHNOLOGY INC.; Package Height: 0.9 MM; Package Size: VQFN16; Package Type: SMD; Part Number: PVWXM
U26 = g_inv_1slot_nc1_a2: IC,7SZ14,SOT353,INVERTER; CLASS: IC; Manufacturer: FAIRCHILD; Manufacturer PN: NC7SZ14P5X; Package Height: 1.1 MM; Package Size: SOT353; Package Type: SMD; Part Number: DT962
C73 = cap: CAP,10UF,20%,16V,X6S,0603; CLASS: DISCRETE; DEVICE: 090729120217; DPN: 3MRV8; Dielectric Type: X6S; Lead Free: Yes; Lifecycle Phase: A Revision; Manufacturer: MURATA ERIE; Manufacturer PN: GRM188C81C106MA73D; Package Height: 40 MIL; Package Size: 0603; Package Type: SMD; Part Number: 3MRV8; ROOM: BRD2; Rev: A00-00; TOLERANCE: 20%; VOLTAGE: 16V
C74 C155 = cap: CAP,2.2UF,10%,16V,X5R,0603; CLASS: DISCRETE; DPN: J6201; Dielectric Type: X5R; Lead Free: Yes; Lifecycle Phase: A Revision; Manufacturer: MURATA ERIE; Manufacturer PN: GRM188R61C225KE15D; Package Height: 40 MIL; Package Size: 0603; Package Type: SMD; Part Number: J6201; ROOM: BRD2; Rev: A00-00; Tolerance: 10%; Voltage: 16V
LBL3 = 2d_label500x437: LABEL,2D BARCODE,.500X.437,TYPE T; DEVICE: 090730100102; Part Number: HP126; ROOM: BRD2; TAG1: 2D BARCODE; TAG2: TYPE T
MH5 MH6 = g_1x1_mh: MT_HOLE_UNPLATED148_288PADS TOP AND BOTTOM_8GND VIAS; BOM_IGNORE: TRUE; CLASS: DISCRETE; DPN: 00000; GND Vias: 8 GND VIAS; Lead Free: N/A; Lifecycle Phase: N/A; Package Height: 1 MIL; Part Number: 090730100124; ROOM: BRD2; Rev: N/A
P_OCP2 = c84edg_amp: [EDGE CARD]CON,EC,168,.6MM,S,G,ST; ALT_SYMBOLS: (CON_AMP_EDGE_ME101681340131X_alt); BOM_IGNORE: TRUE; CLASS: IO; Connector Type: EDGE-CARD; DPN: 00000_7HYMF; Lead Free: N/A; Lifecycle Phase: N/A; Package Height: 0.98 MM; Package Type: EDGE-CARD; Part Number: 7HYMF|EDG; ROOM: BRD2; Rev: N/A
R78 R80 R81 = res: RES,0,1/20W,5%,THKFLM,0201; ALT_SYMBOLS: (R0201_R4,R0201M_FOX); CLASS: DISCRETE; DPN: YY941; Lead Free: Yes; Lifecycle Phase: A Revision; Manufacturer: KOA; Manufacturer PN: RK73Z1HTQTC; Material: Thick Film; Package Height: 0.33 MM; Package Size: 0201; Package Type: SMD; Part Number: YY941; ROOM: BRD2; Rated Power: 50mW; Rev: A00-00; SUB: NP; Tolerance: 5%
R79 = res: RES,4.7K,1/20W,1%,THKFLM,0201; ALT_SYMBOLS: (R0201_R4,R0201M_FOX); CLASS: DISCRETE; DPN: X44H2; Lead Free: Yes; Lifecycle Phase: A Revision; Manufacturer: KOA; Manufacturer PN: RK73H1HTTC4701F; Material: Thick Film; Package Height: 0.33 MM; Package Size: 0201; Package Type: SMD; Part Number: X44H2; ROOM: BRD2; Rated Power: 50mW; Rev: A00-00; Tolerance: 1%
R82 = res: RES,0,1/20W,5%,THKFLM,0201; ALT_SYMBOLS: (R0201_R4,R0201M_FOX); CLASS: DISCRETE; DPN: YY941; Lead Free: Yes; Lifecycle Phase: A Revision; Manufacturer: KOA; Manufacturer PN: RK73Z1HTQTC; Material: Thick Film; Package Height: 0.33 MM; Package Size: 0201; Package Type: SMD; Part Number: YY941; ROOM: BRD2; Rated Power: 50mW; Rev: A00-00; Tolerance: 5%
R166 = res: RES,100K,1/16W,5%,THKFLM,0402; CLASS: DISCRETE; DPN: 92259; Lead Free: Yes; Lifecycle Phase: A Revision; Manufacturer: KOA; Manufacturer PN: RK73B1ETTP104J; Material: Thick Film; Package Height: 16 MIL; Package Size: 0402; Package Type: SMD; Part Number: 92259; ROOM: BRD2; Rated Power: 62.5mW; Rev: A00-00; Tolerance: 5%
TP55-TP83 = g_tp: TEST POINT 1.00X1.50; BOM_IGNORE: TRUE; CLASS: DISCRETE; DPN: 00000; Lead Free: N/A; Lifecycle Phase: N/A; Package Type: SMD; Part Number: 140114160012; ROOM: BRD2; Rev: N/A

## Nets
GND_BD1: C1.2 C2.1 C3.1 C4.1 C5.1 C6.2 C7.2 C8.1 C9.1 C10.2 C13.1 C15.1 C16.2 C20.1 C145.1 C146.1 C147.1 C148.1 C149.1 C163.1 C166.2 DS_BD1_PWR.2(C) MH1.1 MH2.1 P1.2 P2.2 P3.2 P13.2 P_BD1_CLK0_N.2 P_BD1_CLK0_N.3 P_BD1_CLK0_N.4 P_BD1_CLK0_N.5 P_BD1_CLK0_N.6 P_BD1_CLK0_P.2 P_BD1_CLK0_P.3 P_BD1_CLK0_P.4 P_BD1_CLK0_P.5 P_BD1_CLK0_P.6 P_BD1_CLK1_N.2(MH1) P_BD1_CLK1_N.3(MH2) P_BD1_CLK1_N.4(MH3) P_BD1_CLK1_N.5(MH4) P_BD1_CLK1_N.6(MH6) P_BD1_CLK1_P.2(MH1) P_BD1_CLK1_P.3(MH2) P_BD1_CLK1_P.4(MH3) P_BD1_CLK1_P.5(MH4) P_BD1_CLK1_P.6(MH6) P_BD1_CLK2_N.2 P_BD1_CLK2_N.3 P_BD1_CLK2_N.4 P_BD1_CLK2_N.5 P_BD1_CLK2_N.6 P_BD1_CLK2_P.2 P_BD1_CLK2_P.3 P_BD1_CLK2_P.4 P_BD1_CLK2_P.5 P_BD1_CLK2_P.6 P_BD1_CLK3_N.2(MH1) P_BD1_CLK3_N.3(MH2) P_BD1_CLK3_N.4(MH3) P_BD1_CLK3_N.5(MH4) P_BD1_CLK3_N.6(MH6) P_BD1_CLK3_P.2(MH1) P_BD1_CLK3_P.3(MH2) P_BD1_CLK3_P.4(MH3) P_BD1_CLK3_P.5(MH4) P_BD1_CLK3_P.6(MH6) P_BD1_CMTS_N.2 P_BD1_CMTS_N.3 P_BD1_CMTS_N.4 P_BD1_CMTS_N.5 P_BD1_CMTS_N.6 P_BD1_CMTS_P.2 P_BD1_CMTS_P.3 P_BD1_CMTS_P.4 P_BD1_CMTS_P.5 P_BD1_CMTS_P.6 P_BD1_TRIG_IN_N.2(MH1) P_BD1_TRIG_IN_N.3(MH2) P_BD1_TRIG_IN_N.4(MH3) P_BD1_TRIG_IN_N.5(MH4) P_BD1_TRIG_IN_N.6(MH6) P_BD1_TRIG_IN_P.2(MH1) P_BD1_TRIG_IN_P.3(MH2) P_BD1_TRIG_IN_P.4(MH3) P_BD1_TRIG_IN_P.5(MH4) P_BD1_TRIG_IN_P.6(MH6) P_CPU_OCP_0_N.2 P_CPU_OCP_0_N.3 P_CPU_OCP_0_N.4 P_CPU_OCP_0_N.5 P_CPU_OCP_0_N.6 P_CPU_OCP_0_P.2 P_CPU_OCP_0_P.3 P_CPU_OCP_0_P.4 P_CPU_OCP_0_P.5 P_CPU_OCP_0_P.6 P_CPU_OCP_1_N.2 P_CPU_OCP_1_N.3 P_CPU_OCP_1_N.4 P_CPU_OCP_1_N.5 P_CPU_OCP_1_N.6 P_CPU_OCP_1_P.2 P_CPU_OCP_1_P.3 P_CPU_OCP_1_P.4 P_CPU_OCP_1_P.5 P_CPU_OCP_1_P.6 P_CPU_OCP_2_N.2 P_CPU_OCP_2_N.3 P_CPU_OCP_2_N.4 P_CPU_OCP_2_N.5 P_CPU_OCP_2_N.6 P_CPU_OCP_2_P.2 P_CPU_OCP_2_P.3 P_CPU_OCP_2_P.4 P_CPU_OCP_2_P.5 P_CPU_OCP_2_P.6 P_CPU_OCP_3_N.2 P_CPU_OCP_3_N.3 P_CPU_OCP_3_N.4 P_CPU_OCP_3_N.5 P_CPU_OCP_3_N.6 P_CPU_OCP_3_P.2 P_CPU_OCP_3_P.3 P_CPU_OCP_3_P.4 P_CPU_OCP_3_P.5 P_CPU_OCP_3_P.6 P_CPU_OCP_4_N.2 P_CPU_OCP_4_N.3 P_CPU_OCP_4_N.4 P_CPU_OCP_4_N.5 P_CPU_OCP_4_N.6 P_CPU_OCP_4_P.2 P_CPU_OCP_4_P.3 P_CPU_OCP_4_P.4 P_CPU_OCP_4_P.5 P_CPU_OCP_4_P.6 P_CPU_OCP_5_N.2 P_CPU_OCP_5_N.3 P_CPU_OCP_5_N.4 P_CPU_OCP_5_N.5 P_CPU_OCP_5_N.6 P_CPU_OCP_5_P.2 P_CPU_OCP_5_P.3 P_CPU_OCP_5_P.4 P_CPU_OCP_5_P.5 P_CPU_OCP_5_P.6 P_CPU_OCP_6_N.2 P_CPU_OCP_6_N.3 P_CPU_OCP_6_N.4 P_CPU_OCP_6_N.5 P_CPU_OCP_6_N.6 P_CPU_OCP_6_P.2 P_CPU_OCP_6_P.3 P_CPU_OCP_6_P.4 P_CPU_OCP_6_P.5 P_CPU_OCP_6_P.6 P_CPU_OCP_7_N.2 P_CPU_OCP_7_N.3 P_CPU_OCP_7_N.4 P_CPU_OCP_7_N.5 P_CPU_OCP_7_N.6 P_CPU_OCP_7_P.2 P_CPU_OCP_7_P.3 P_CPU_OCP_7_P.4 P_CPU_OCP_7_P.5 P_CPU_OCP_7_P.6 P_OCP1.A1 P_OCP1.A2 P_OCP1.A3 P_OCP1.A4 P_OCP1.A5 P_OCP1.A6 P_OCP1.A13 P_OCP1.A16 P_OCP1.A19 P_OCP1.A22 P_OCP1.A25 P_OCP1.A28 P_OCP1.A29 P_OCP1.A32 P_OCP1.A35 P_OCP1.A38 P_OCP1.A41 P_OCP1.A43 P_OCP1.A46 P_OCP1.A49 P_OCP1.A52 P_OCP1.A55 P_OCP1.A58 P_OCP1.A61 P_OCP1.A64 P_OCP1.A67 P_OCP1.B13 P_OCP1.B16 P_OCP1.B19 P_OCP1.B22 P_OCP1.B25 P_OCP1.B28 P_OCP1.B29 P_OCP1.B32 P_OCP1.B35 P_OCP1.B38 P_OCP1.B41 P_OCP1.B43 P_OCP1.B46 P_OCP1.B49 P_OCP1.B52 P_OCP1.B55 P_OCP1.B58 P_OCP1.B61 P_OCP1.B64 P_OCP1.B67 P_OCP1.OCP_A10 P_OCP1.OCP_A13 P_OCP1.OCP_B10 P_OCP1.OCP_B13 P_OCP_CPU_0_N.2(MH1) P_OCP_CPU_0_N.3(MH2) P_OCP_CPU_0_N.4(MH3) P_OCP_CPU_0_N.5(MH4) P_OCP_CPU_0_N.6(MH6) P_OCP_CPU_0_P.2(MH1) P_OCP_CPU_0_P.3(MH2) P_OCP_CPU_0_P.4(MH3) P_OCP_CPU_0_P.5(MH4) P_OCP_CPU_0_P.6(MH6) P_OCP_CPU_1_N.2(MH1) P_OCP_CPU_1_N.3(MH2) P_OCP_CPU_1_N.4(MH3) P_OCP_CPU_1_N.5(MH4) P_OCP_CPU_1_N.6(MH6) P_OCP_CPU_1_P.2(MH1) P_OCP_CPU_1_P.3(MH2) P_OCP_CPU_1_P.4(MH3) P_OCP_CPU_1_P.5(MH4) P_OCP_CPU_1_P.6(MH6) P_OCP_CPU_2_N.2(MH1) P_OCP_CPU_2_N.3(MH2) P_OCP_CPU_2_N.4(MH3) P_OCP_CPU_2_N.5(MH4) P_OCP_CPU_2_N.6(MH6) P_OCP_CPU_2_P.2(MH1) P_OCP_CPU_2_P.3(MH2) P_OCP_CPU_2_P.4(MH3) P_OCP_CPU_2_P.5(MH4) P_OCP_CPU_2_P.6(MH6) P_OCP_CPU_3_N.2(MH1) P_OCP_CPU_3_N.3(MH2) P_OCP_CPU_3_N.4(MH3) P_OCP_CPU_3_N.5(MH4) P_OCP_CPU_3_N.6(MH6) P_OCP_CPU_3_P.2(MH1) P_OCP_CPU_3_P.3(MH2) P_OCP_CPU_3_P.4(MH3) P_OCP_CPU_3_P.5(MH4) P_OCP_CPU_3_P.6(MH6) P_OCP_CPU_4_N.2(MH1) P_OCP_CPU_4_N.3(MH2) P_OCP_CPU_4_N.4(MH3) P_OCP_CPU_4_N.5(MH4) P_OCP_CPU_4_N.6(MH6) P_OCP_CPU_4_P.2(MH1) P_OCP_CPU_4_P.3(MH2) P_OCP_CPU_4_P.4(MH3) P_OCP_CPU_4_P.5(MH4) P_OCP_CPU_4_P.6(MH6) P_OCP_CPU_5_N.2(MH1) P_OCP_CPU_5_N.3(MH2) P_OCP_CPU_5_N.4(MH3) P_OCP_CPU_5_N.5(MH4) P_OCP_CPU_5_N.6(MH6) P_OCP_CPU_5_P.2(MH1) P_OCP_CPU_5_P.3(MH2) P_OCP_CPU_5_P.4(MH3) P_OCP_CPU_5_P.5(MH4) P_OCP_CPU_5_P.6(MH6) P_OCP_CPU_6_N.2(MH1) P_OCP_CPU_6_N.3(MH2) P_OCP_CPU_6_N.4(MH3) P_OCP_CPU_6_N.5(MH4) P_OCP_CPU_6_N.6(MH6) P_OCP_CPU_6_P.2(MH1) P_OCP_CPU_6_P.3(MH2) P_OCP_CPU_6_P.4(MH3) P_OCP_CPU_6_P.5(MH4) P_OCP_CPU_6_P.6(MH6) P_OCP_CPU_7_N.2(MH1) P_OCP_CPU_7_N.3(MH2) P_OCP_CPU_7_N.4(MH3) P_OCP_CPU_7_N.5(MH4) P_OCP_CPU_7_N.6(MH6) P_OCP_CPU_7_P.2(MH1) P_OCP_CPU_7_P.3(MH2) P_OCP_CPU_7_P.4(MH3) P_OCP_CPU_7_P.5(MH4) P_OCP_CPU_7_P.6(MH6) Q1.2(S) SW1.2 U1.3(GND) U2.3(GND) U3.3(GND) U4.1(GND) U5.3(GND) U6.3(GND) U7.3(GND) U24.9(GND) U24.17(EPAD) U26.3(GND)
GND_BD2: C73.2 C74.1 C155.1 MH5.1 MH6.1 P_OCP2.A1 P_OCP2.A2 P_OCP2.A3 P_OCP2.A4 P_OCP2.A5 P_OCP2.A6 P_OCP2.A13 P_OCP2.A16 P_OCP2.A19 P_OCP2.A22 P_OCP2.A25 P_OCP2.A28 P_OCP2.A29 P_OCP2.A32 P_OCP2.A35 P_OCP2.A38 P_OCP2.A41 P_OCP2.A43 P_OCP2.A46 P_OCP2.A49 P_OCP2.A52 P_OCP2.A55 P_OCP2.A58 P_OCP2.A61 P_OCP2.A64 P_OCP2.A67 P_OCP2.B13 P_OCP2.B16 P_OCP2.B19 P_OCP2.B22 P_OCP2.B25 P_OCP2.B28 P_OCP2.B29 P_OCP2.B32 P_OCP2.B35 P_OCP2.B38 P_OCP2.B41 P_OCP2.B43 P_OCP2.B46 P_OCP2.B49 P_OCP2.B52 P_OCP2.B55 P_OCP2.B58 P_OCP2.B61 P_OCP2.B64 P_OCP2.B67 P_OCP2.OCP_A10 P_OCP2.OCP_A13 P_OCP2.OCP_B10 P_OCP2.OCP_B13 ; also on sheet 8 9 10
BD1_555_DISCHARGE: C6.1 R11.1 R13.1 U4.6(THRESHOLD) U4.7(DISCHARGE)
BD1_555_OUT: R16.2 R18.2 U4.3(OUT)
BD1_555_OUT_JP: P3.1 R16.1
BD1_555_RST_N: C7.1 R15.1 U4.4(RESET_N)
BD1_555_TRI: R8.2 R14.2 U4.2(TRIGGER_N)
BD1_AUX_PWR_EN: P_OCP1.B12 TP26.TEST
BD1_BIF0_N: P_OCP1.B7 TP18.TEST
BD1_BIF1_N: P_OCP1.B8 TP20.TEST
BD1_BIF2_N: P_OCP1.B9 TP22.TEST
BD1_BTN_NC: R7.1 R9.1 SW1.1 U1.1(A)
BD1_BTN_NO: R8.1 R17.1 SW1.3 U6.2(B)
BD1_BUS_SEL: C163.2 P13.1 Q1.1(G) R7.2 R18.1 R158.1 U26.2(A)
BD1_CLK_NCSI: P_OCP1.OCP_A14 TP17.TEST
BD1_MAIN_PWR_EN: P_OCP1.OCP_B2 TP27.TEST
BD1_NCSI_ARBIN: P_OCP1.OCP_A4 TP8.TEST
BD1_NCSI_ARBOUT: P_OCP1.OCP_A5 TP9.TEST
BD1_NCSI_CRS_DV: P_OCP1.OCP_B14 TP16.TEST
BD1_NCSI_RXD0: P_OCP1.OCP_B9 TP14.TEST
BD1_NCSI_RXD1: P_OCP1.OCP_B8 TP12.TEST
BD1_NCSI_TXD0: P_OCP1.OCP_A9 TP15.TEST
BD1_NCSI_TXD1: P_OCP1.OCP_A8 TP13.TEST
BD1_NCSI_TXEN: P_OCP1.OCP_A7 TP11.TEST
BD1_NIC_PWR_GOOD: P_OCP1.OCP_B1 R5.1
BD1_PERST0_N: P_OCP1.B10 TP24.TEST
BD1_PERST1_N: P_OCP1.A11 TP25.TEST
BD1_PERST2_N: P_OCP1.OCP_A1 TP3.TEST
BD1_PERST3_N: P_OCP1.OCP_A2 TP4.TEST
BD1_PRSNTA_N: P_OCP1.A10 R1.2 R2.2 R3.2 R6.2
BD1_PRSNTB0_N: P_OCP1.B42 R1.1
BD1_PRSNTB1_N: P_OCP1.A42 R2.1
BD1_PRSNTB2_N: P_OCP1.A12 R3.1
BD1_PRSNTB3_N: P_OCP1.B70 R6.1
BD1_PWRBRK_N: P_OCP1.A70 R164.1
BD1_REFCLK0_DN: P_BD1_CLK0_N.1 P_OCP1.B14
BD1_REFCLK0_DP: P_BD1_CLK0_P.1 P_OCP1.B15
BD1_REFCLK1_DN: P_BD1_CLK1_N.1 P_OCP1.A14
BD1_REFCLK1_DP: P_BD1_CLK1_P.1 P_OCP1.A15
BD1_REFCLK2_DN: P_BD1_CLK2_N.1 P_OCP1.OCP_B11
BD1_REFCLK2_DP: P_BD1_CLK2_P.1 P_OCP1.OCP_B12
BD1_REFCLK3_DN: P_BD1_CLK3_N.1 P_OCP1.OCP_A11
BD1_REFCLK3_DP: P_BD1_CLK3_P.1 P_OCP1.OCP_A12
BD1_SCAN_CLK: P_OCP1.OCP_B6 TP1.TEST
BD1_SCAN_DATA_IN: P_OCP1.OCP_B4 TP7.TEST
BD1_SCAN_DATA_OUT: P_OCP1.OCP_B5 TP10.TEST
BD1_SCAN_LD_N: P_OCP1.OCP_B3 TP5.TEST
BD1_SLOT_ID: P_OCP1.OCP_B7 TP2.TEST
BD1_SMB_CLK: P_OCP1.A7 TP19.TEST
BD1_SMB_RST_N: P_OCP1.A9 TP23.TEST
BD1_SMB_SDA: P_OCP1.A8 TP21.TEST
BD1_WAKE_N: P_OCP1.OCP_A3 TP6.TEST
BD2_AUX_PWR_EN: P_OCP2.B12 TP81.TEST
BD2_BIF0_N: P_OCP2.B7 TP72.TEST
BD2_BIF1_N: P_OCP2.B8 TP73.TEST
BD2_BIF2_N: P_OCP2.B9 TP77.TEST
BD2_CLK_NCSI: P_OCP2.OCP_A14 TP71.TEST
BD2_MAIN_PWR_EN: P_OCP2.OCP_B2 TP56.TEST
BD2_NCSI_ARBIN: P_OCP2.OCP_A4 TP74.TEST
BD2_NCSI_ARBOUT: P_OCP2.OCP_A5 TP62.TEST
BD2_NCSI_CRS_DV: P_OCP2.OCP_B14 TP70.TEST
BD2_NCSI_RXD0: P_OCP2.OCP_B9 TP68.TEST
BD2_NCSI_RXD1: P_OCP2.OCP_B8 TP66.TEST
BD2_NCSI_TXD0: P_OCP2.OCP_A9 TP69.TEST
BD2_NCSI_TXD1: P_OCP2.OCP_A8 TP67.TEST
BD2_NCSI_TXEN: P_OCP2.OCP_A7 TP65.TEST
BD2_NIC_PWR_GOOD: P_OCP2.OCP_B1 R79.1
BD2_PE_OCP_CPU_0_DN: P_OCP2.A17 ; also on sheet 10
BD2_PE_OCP_CPU_0_DP: P_OCP2.A18 ; also on sheet 10
BD2_PERST0_N: P_OCP2.B10 TP79.TEST
BD2_PERST1_N: P_OCP2.A11 TP80.TEST
BD2_PERST2_N: P_OCP2.OCP_A1 TP55.TEST
BD2_PERST3_N: P_OCP2.OCP_A2 TP57.TEST
BD2_PRSNTA_N: P_OCP2.A10 R78.2 R80.2 R81.2 R82.2
BD2_PRSNTB0_N: P_OCP2.B42 R78.1
BD2_PRSNTB1_N: P_OCP2.A42 R80.1
BD2_PRSNTB2_N: P_OCP2.A12 R81.1
BD2_PRSNTB3_N: P_OCP2.B70 R82.1
BD2_PWRBRK_N: P_OCP2.A70 R166.1
BD2_REFCLK0_DN: P_OCP2.B14 ; also on sheet 8
BD2_REFCLK0_DP: P_OCP2.B15 ; also on sheet 8
BD2_REFCLK1_DN: P_OCP2.A14 ; also on sheet 8
BD2_REFCLK1_DP: P_OCP2.A15 ; also on sheet 8
BD2_REFCLK2_DN: P_OCP2.OCP_B11 ; also on sheet 8
BD2_REFCLK2_DP: P_OCP2.OCP_B12 ; also on sheet 8
BD2_REFCLK3_DN: P_OCP2.OCP_A11 TP82.TEST
BD2_REFCLK3_DP: P_OCP2.OCP_A12 TP83.TEST
BD2_SCAN_CLK: P_OCP2.OCP_B6 TP63.TEST
BD2_SCAN_DATA_IN: P_OCP2.OCP_B4 TP60.TEST
BD2_SCAN_DATA_OUT: P_OCP2.OCP_B5 TP61.TEST
BD2_SCAN_LD_N: P_OCP2.OCP_B3 TP58.TEST
BD2_SLOT_ID: P_OCP2.OCP_B7 TP64.TEST
BD2_SLOT_ID1: P_OCP2.OCP_A6
BD2_SMB_CLK: P_OCP2.A7 TP75.TEST
BD2_SMB_RST_N: P_OCP2.A9 TP78.TEST
BD2_SMB_SDA: P_OCP2.A8 TP76.TEST
BD2_WAKE_N: P_OCP2.OCP_A3 TP59.TEST
CLK1_HOST_TO_TRIGGER_DN: C149.2 P_BD1_TRIG_IN_N.1 U24.2(IN_n)
CLK1_HOST_TO_TRIGGER_DP: C148.2 P_BD1_TRIG_IN_P.1 U24.1(IN_p)
CLK1_TRIG_SIGNAL_C_DN: C12.1 R21.1
CLK1_TRIG_SIGNAL_C_DP: C11.1 R19.1
CLK1_TRIG_SIGNAL_DN: C12.2 U24.11(OUT0_n)
CLK1_TRIG_SIGNAL_DP: C11.2 U24.10(OUT0_p)
CLK1_TRIG_SIGNAL_R_DN: P_BD1_CMTS_N.1 R21.2
CLK1_TRIG_SIGNAL_R_DP: P_BD1_CMTS_P.1 R19.2
NC1_A6_SLOT_ID1: P_OCP1.OCP_A6
NC1_A68: P_OCP1.A68
NC1_A69: P_OCP1.A69
NC1_B68: P_OCP1.B68
NC1_B69: P_OCP1.B69
NC2_A68: P_OCP2.A68
NC2_A69: P_OCP2.A69
NC2_B68: P_OCP2.B68
NC2_B69: P_OCP2.B69
PE_CPU_OCP_0_DN: P_CPU_OCP_0_N.1 P_OCP1.B17
PE_CPU_OCP_0_DP: P_CPU_OCP_0_P.1 P_OCP1.B18
PE_CPU_OCP_1_DN: P_CPU_OCP_1_N.1 P_OCP1.B20
PE_CPU_OCP_1_DP: P_CPU_OCP_1_P.1 P_OCP1.B21
PE_CPU_OCP_2_DN: P_CPU_OCP_2_N.1 P_OCP1.B23
PE_CPU_OCP_2_DP: P_CPU_OCP_2_P.1 P_OCP1.B24
PE_CPU_OCP_3_DN: P_CPU_OCP_3_N.1 P_OCP1.B26
PE_CPU_OCP_3_DP: P_CPU_OCP_3_P.1 P_OCP1.B27
PE_CPU_OCP_4_DN: P_CPU_OCP_4_N.1 P_OCP1.B30
PE_CPU_OCP_4_DP: P_CPU_OCP_4_P.1 P_OCP1.B31
PE_CPU_OCP_5_DN: P_CPU_OCP_5_N.1 P_OCP1.B33
PE_CPU_OCP_5_DP: P_CPU_OCP_5_P.1 P_OCP1.B34
PE_CPU_OCP_6_DN: P_CPU_OCP_6_N.1 P_OCP1.B36
PE_CPU_OCP_6_DP: P_CPU_OCP_6_P.1 P_OCP1.B37
PE_CPU_OCP_7_DN: P_CPU_OCP_7_N.1 P_OCP1.B39
PE_CPU_OCP_7_DP: P_CPU_OCP_7_P.1 P_OCP1.B40
PE_CPU_OCP_8_DN: P_OCP2.B44 ; also on sheet 9
PE_CPU_OCP_8_DP: P_OCP2.B45 ; also on sheet 9
PE_CPU_OCP_9_DN: P_OCP2.B47 ; also on sheet 9
PE_CPU_OCP_9_DP: P_OCP2.B48 ; also on sheet 9
PE_CPU_OCP_10_DN: P_OCP2.B50 ; also on sheet 9
PE_CPU_OCP_10_DP: P_OCP2.B51 ; also on sheet 9
PE_CPU_OCP_11_DN: P_OCP2.B53 ; also on sheet 9
PE_CPU_OCP_11_DP: P_OCP2.B54 ; also on sheet 9
PE_CPU_OCP_12_DN: P_OCP2.B56 ; also on sheet 10
PE_CPU_OCP_12_DP: P_OCP2.B57 ; also on sheet 10
PE_CPU_OCP_13_DN: P_OCP2.B59 ; also on sheet 10
PE_CPU_OCP_13_DP: P_OCP2.B60 ; also on sheet 10
PE_CPU_OCP_14_DN: P_OCP2.B62 ; also on sheet 10
PE_CPU_OCP_14_DP: P_OCP2.B63 ; also on sheet 10
PE_CPU_OCP_15_DN: P_OCP2.B65 ; also on sheet 10
PE_CPU_OCP_15_DP: P_OCP2.B66 ; also on sheet 10
PE_OCP_CPU_0_DN: P_OCP1.A17 P_OCP_CPU_0_N.1
PE_OCP_CPU_0_DP: P_OCP1.A18 P_OCP_CPU_0_P.1
PE_OCP_CPU_1_DN: P_OCP1.A20 P_OCP_CPU_1_N.1
PE_OCP_CPU_1_DP: P_OCP1.A21 P_OCP_CPU_1_P.1
PE_OCP_CPU_2_DN: P_OCP1.A23 P_OCP_CPU_2_N.1
PE_OCP_CPU_2_DP: P_OCP1.A24 P_OCP_CPU_2_P.1
PE_OCP_CPU_3_DN: P_OCP1.A26 P_OCP_CPU_3_N.1
PE_OCP_CPU_3_DP: P_OCP1.A27 P_OCP_CPU_3_P.1
PE_OCP_CPU_4_DN: P_OCP1.A30 P_OCP_CPU_4_N.1
PE_OCP_CPU_4_DP: P_OCP1.A31 P_OCP_CPU_4_P.1
PE_OCP_CPU_5_DN: P_OCP1.A33 P_OCP_CPU_5_N.1
PE_OCP_CPU_5_DP: P_OCP1.A34 P_OCP_CPU_5_P.1
PE_OCP_CPU_6_DN: P_OCP1.A36 P_OCP_CPU_6_N.1
PE_OCP_CPU_6_DP: P_OCP1.A37 P_OCP_CPU_6_P.1
PE_OCP_CPU_7_DN: P_OCP1.A39 P_OCP_CPU_7_N.1
PE_OCP_CPU_7_DP: P_OCP1.A40 P_OCP_CPU_7_P.1
PE_OCP_CPU_8_DN: P_OCP2.A44 ; also on sheet 9
PE_OCP_CPU_8_DP: P_OCP2.A45 ; also on sheet 9
PE_OCP_CPU_9_DN: P_OCP2.A47 ; also on sheet 9
PE_OCP_CPU_9_DP: P_OCP2.A48 ; also on sheet 9
PE_OCP_CPU_10_DN: P_OCP2.A50 ; also on sheet 9
PE_OCP_CPU_10_DP: P_OCP2.A51 ; also on sheet 9
PE_OCP_CPU_11_DN: P_OCP2.A53 ; also on sheet 9
PE_OCP_CPU_11_DP: P_OCP2.A54 ; also on sheet 9
PE_OCP_CPU_12_DN: P_OCP2.A56 ; also on sheet 10
PE_OCP_CPU_12_DP: P_OCP2.A57 ; also on sheet 10
PE_OCP_CPU_13_DN: P_OCP2.A59 ; also on sheet 10
PE_OCP_CPU_13_DP: P_OCP2.A60 ; also on sheet 10
PE_OCP_CPU_14_DN: P_OCP2.A62 ; also on sheet 10
PE_OCP_CPU_14_DP: P_OCP2.A63 ; also on sheet 10
PE_OCP_CPU_15_DN: P_OCP2.A65 ; also on sheet 10
PE_OCP_CPU_15_DP: P_OCP2.A66 ; also on sheet 10
V_3P3AUX_1: C1.1 C2.2 C3.2 C4.2 C5.2 C8.2 C9.2 C13.2 C15.2 C16.1 C20.2 C146.2 C147.2 C166.1 P_OCP1.B11 R5.2 R9.2 R11.2 R13.2 R15.2 R17.2 R20.1 R158.2 R164.2 R167.1 U1.5(VCC) U2.5(VCC) U3.5(VCC) U4.8(V+) U5.5(VCC) U6.5(VCC) U7.5(VCC) U24.13(VDD) U26.5(VCC)
V_3P3AUX_2: C73.1 C74.2 P_OCP2.B11 R79.2 R166.2 ; also on sheet 8
V_12V_1: C145.2 C150.2 P_OCP1.B1 P_OCP1.B2 P_OCP1.B3 P_OCP1.B4 P_OCP1.B5 P_OCP1.B6 R154.2
V_12V_2: C155.2 P_OCP2.B1 P_OCP2.B2 P_OCP2.B3 P_OCP2.B4 P_OCP2.B5 P_OCP2.B6 ; also on sheet 8
N16712697: R12.1 U1.4(Y) U2.1(A) U3.1(A) U5.1(A) U5.2(B) U6.1(A)
N16712704: P2.1 R12.2
N16712845: U1.2(B) U6.4(Y)
N16713263: U2.4(Y) U3.2(B) U7.1(A)
N16713357: U2.2(B) U7.4(Y)
N16713385: C10.1 U5.4(Y) U7.2(B)
N16713764: R10.1 R14.1 U3.4(Y)
N16713990: P1.1 R10.2
N16720108: DS_BD1_PWR.1(A) R20.2
N16866749: DS_BD1_TRIG.1(A) R154.1
N16866751: C150.1 DS_BD1_TRIG.2(C) Q1.3(D)
N17127453: U24.12(OE0b) U26.4(Y)
N17130541: R167.2 U24.16(OE1b)

Not connected (* = marked no-connect by the designer): LBL1 1(NC); LBL3 1(NC); P_OCP1 A44 A45 A47 A48 A50 A51 A53 A54 A56 A57 A59 A60 A62 A63 A65 A66 B44 B45 B47 B48 B50 B51 B53 B54 B56 B57 B59 B60 B62 B63 B65 B66; P_OCP2 A20 A21 A23 A24 A26 A27 A30 A31 A33 A34 A36 A37 A39 A40 B17 B18 B20 B21 B23 B24 B26 B27 B30 B31 B33 B34 B36 B37 B39 B40; U4 5(CNTRL_VLT)*; U24 3(NC_1)* 4(NC_2)* 5(NC_3)* 6(NC_4)* 7(NC_5)* 8(NC_6)* 14(OUT1_p)* 15(OUT1_n)*; U26 1(NC)*

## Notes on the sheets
sheet 1
- OCP 3.0 - PCIe CLB Gen 5 - X02
- Table of Contents
  Page 1: Title, Block Diagram
  Page 2: Stackup
  Page 3: Brd1 0-7: OCP Edge Conn
  Page 4: Brd1 0-7: CMTS ckt
  Page 5: Brd1 0-3: SMPs
  Page 6: Brd1 4-7: SMPs
  Page 7: Brd3 8-15: OCP Edge Conn
  Page 8: Brd3 8-15: CMTS ckt
  Page 9: Brd3 8-11: SMPs
  Page 10: Brd3 12-15: SMPs
  Page 11: Coupons
  Page 12: Calibration Board
- PWA: 83DG8
  PWB: RX1NY
  Sch: C7D95
- Change History:
  X00 - Initial design
  X01 - Schematic updated for new MMPX connectors, new stackup, CMTS circuit, Gen 5 capable clock buffer
  X02 - PCB material information updated (page 2), no schematic changes
sheet 2
- Stackup
sheet 3
- Board 1 - Rx/Tx Lanes 0-7
- PRSNTB[3:0]_N = 1110 -> x8 link
- P01: pin A6 is now SLOT ID1
- Faceplate Mtg Holes
- P01: moved PWRBRK_N to pin A70
- ROOM = BRD1
sheet 4
- RSVD TEST
- Board 1 - Rx/Tx Lanes 0-7 (cont)
- CMTS OUT
- CMTS IN
- TRIG LED
- PWR LED
- INPUT REFCLKS
- ROOM = BRD1
sheet 5
- Board 1 - Rx/Tx Lanes 0-7 (cont)
- CPU RX
- CPU TX
- ROOM = BRD1
sheet 6
- Board 1 - Rx/Tx Lanes 0-7 (cont)
- CPU RX
- CPU TX
- ROOM = BRD1
sheet 7
- Board 2 - Rx/Tx Lanes 8-15
- PRSNTB[3:0]_N = 1110 -> x8 link
- P01: pin A6 is now SLOT ID1
- Faceplate Mtg Holes
- P01: moved PWRBRK_N to pin A70
- ROOM = BRD2
